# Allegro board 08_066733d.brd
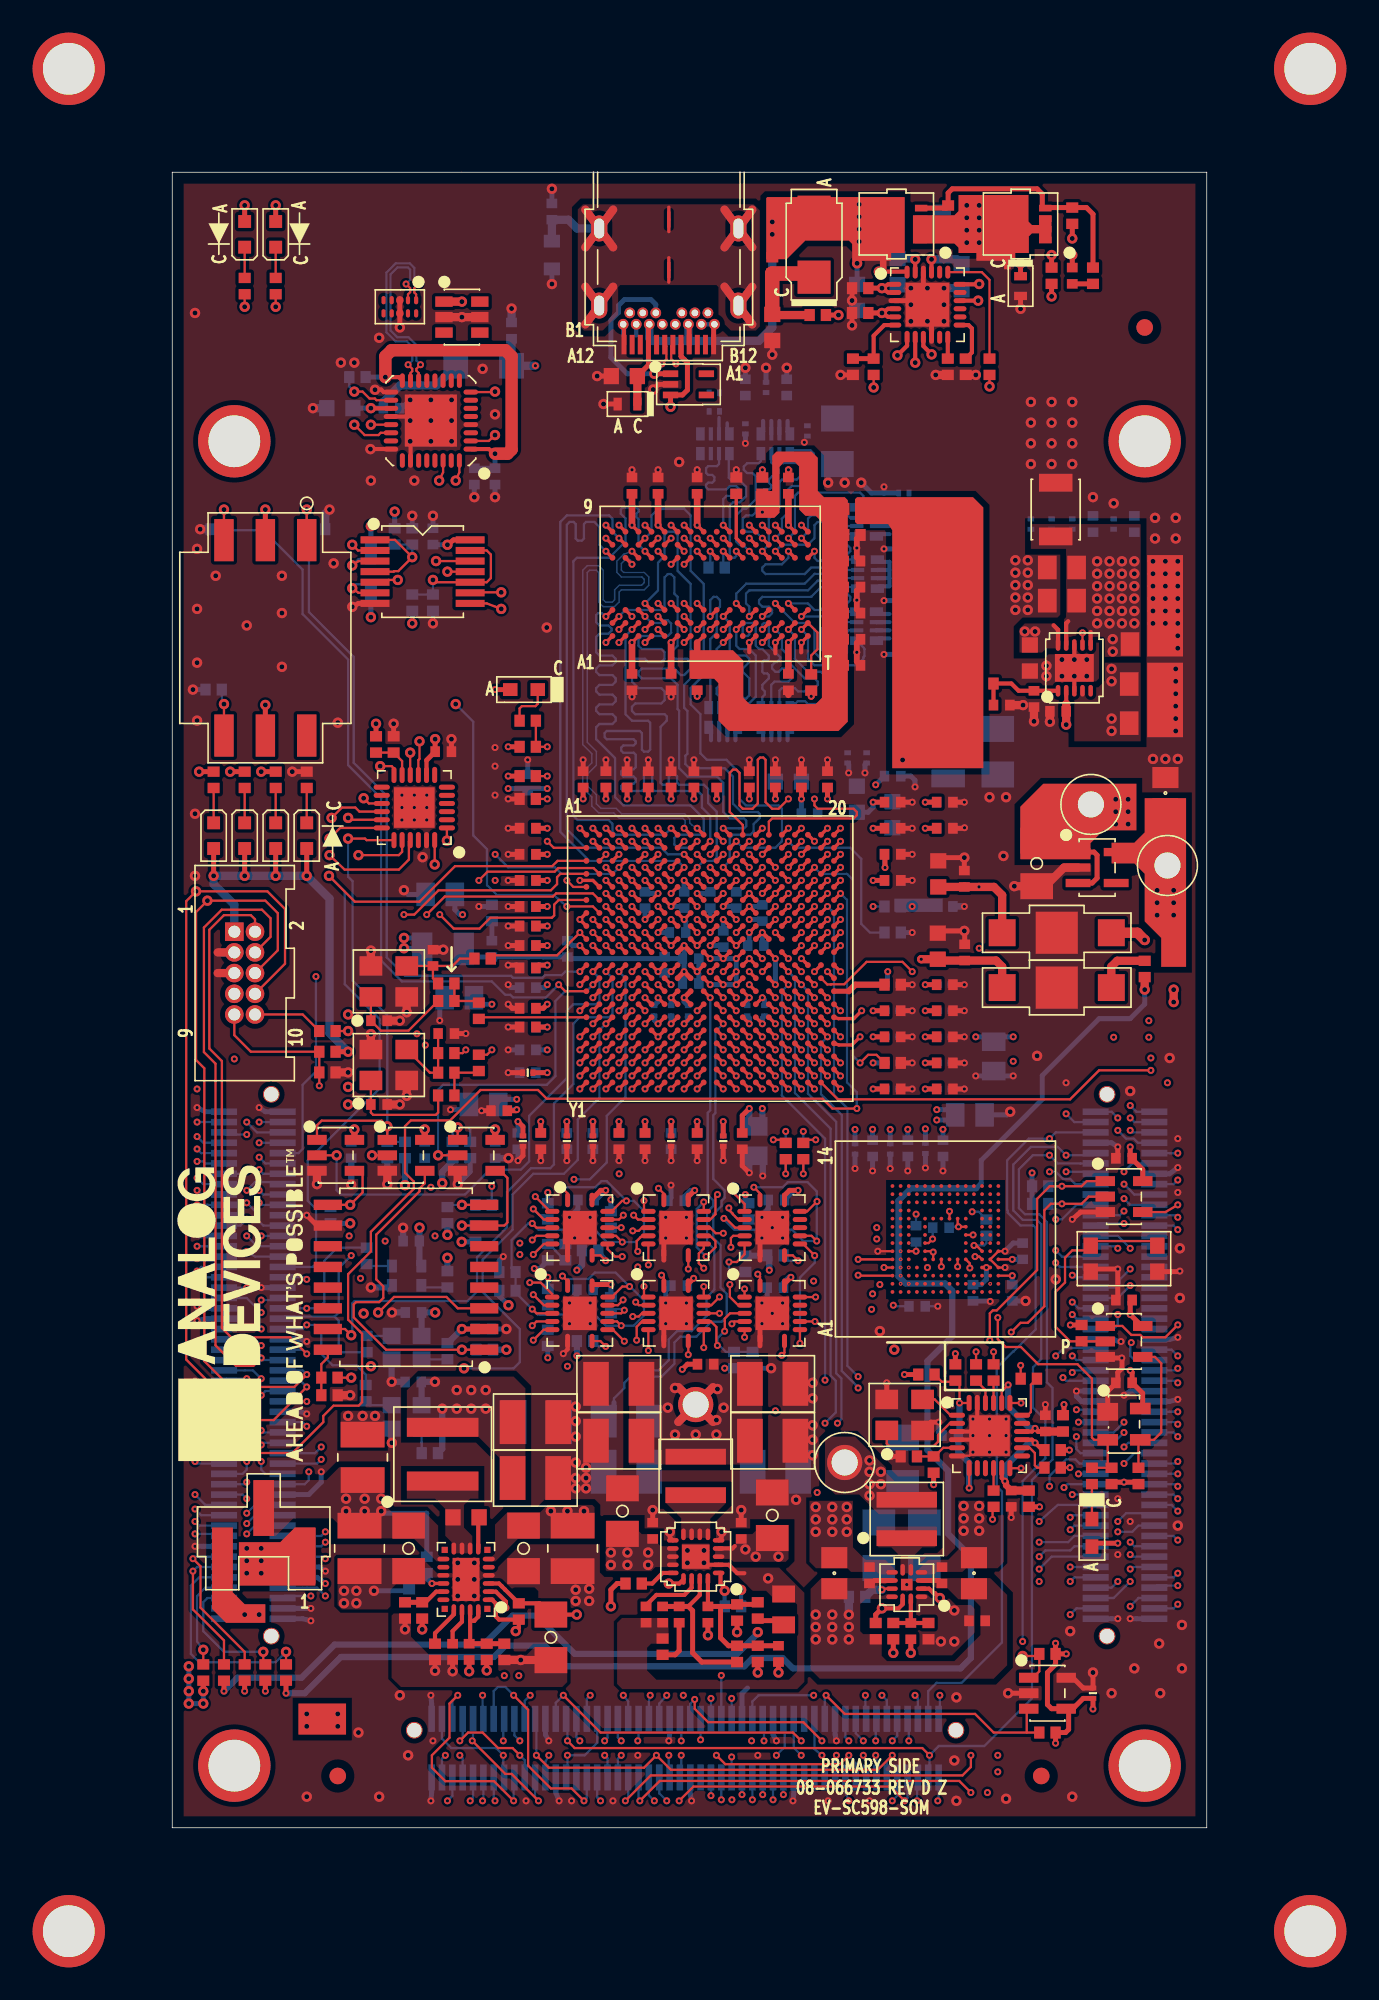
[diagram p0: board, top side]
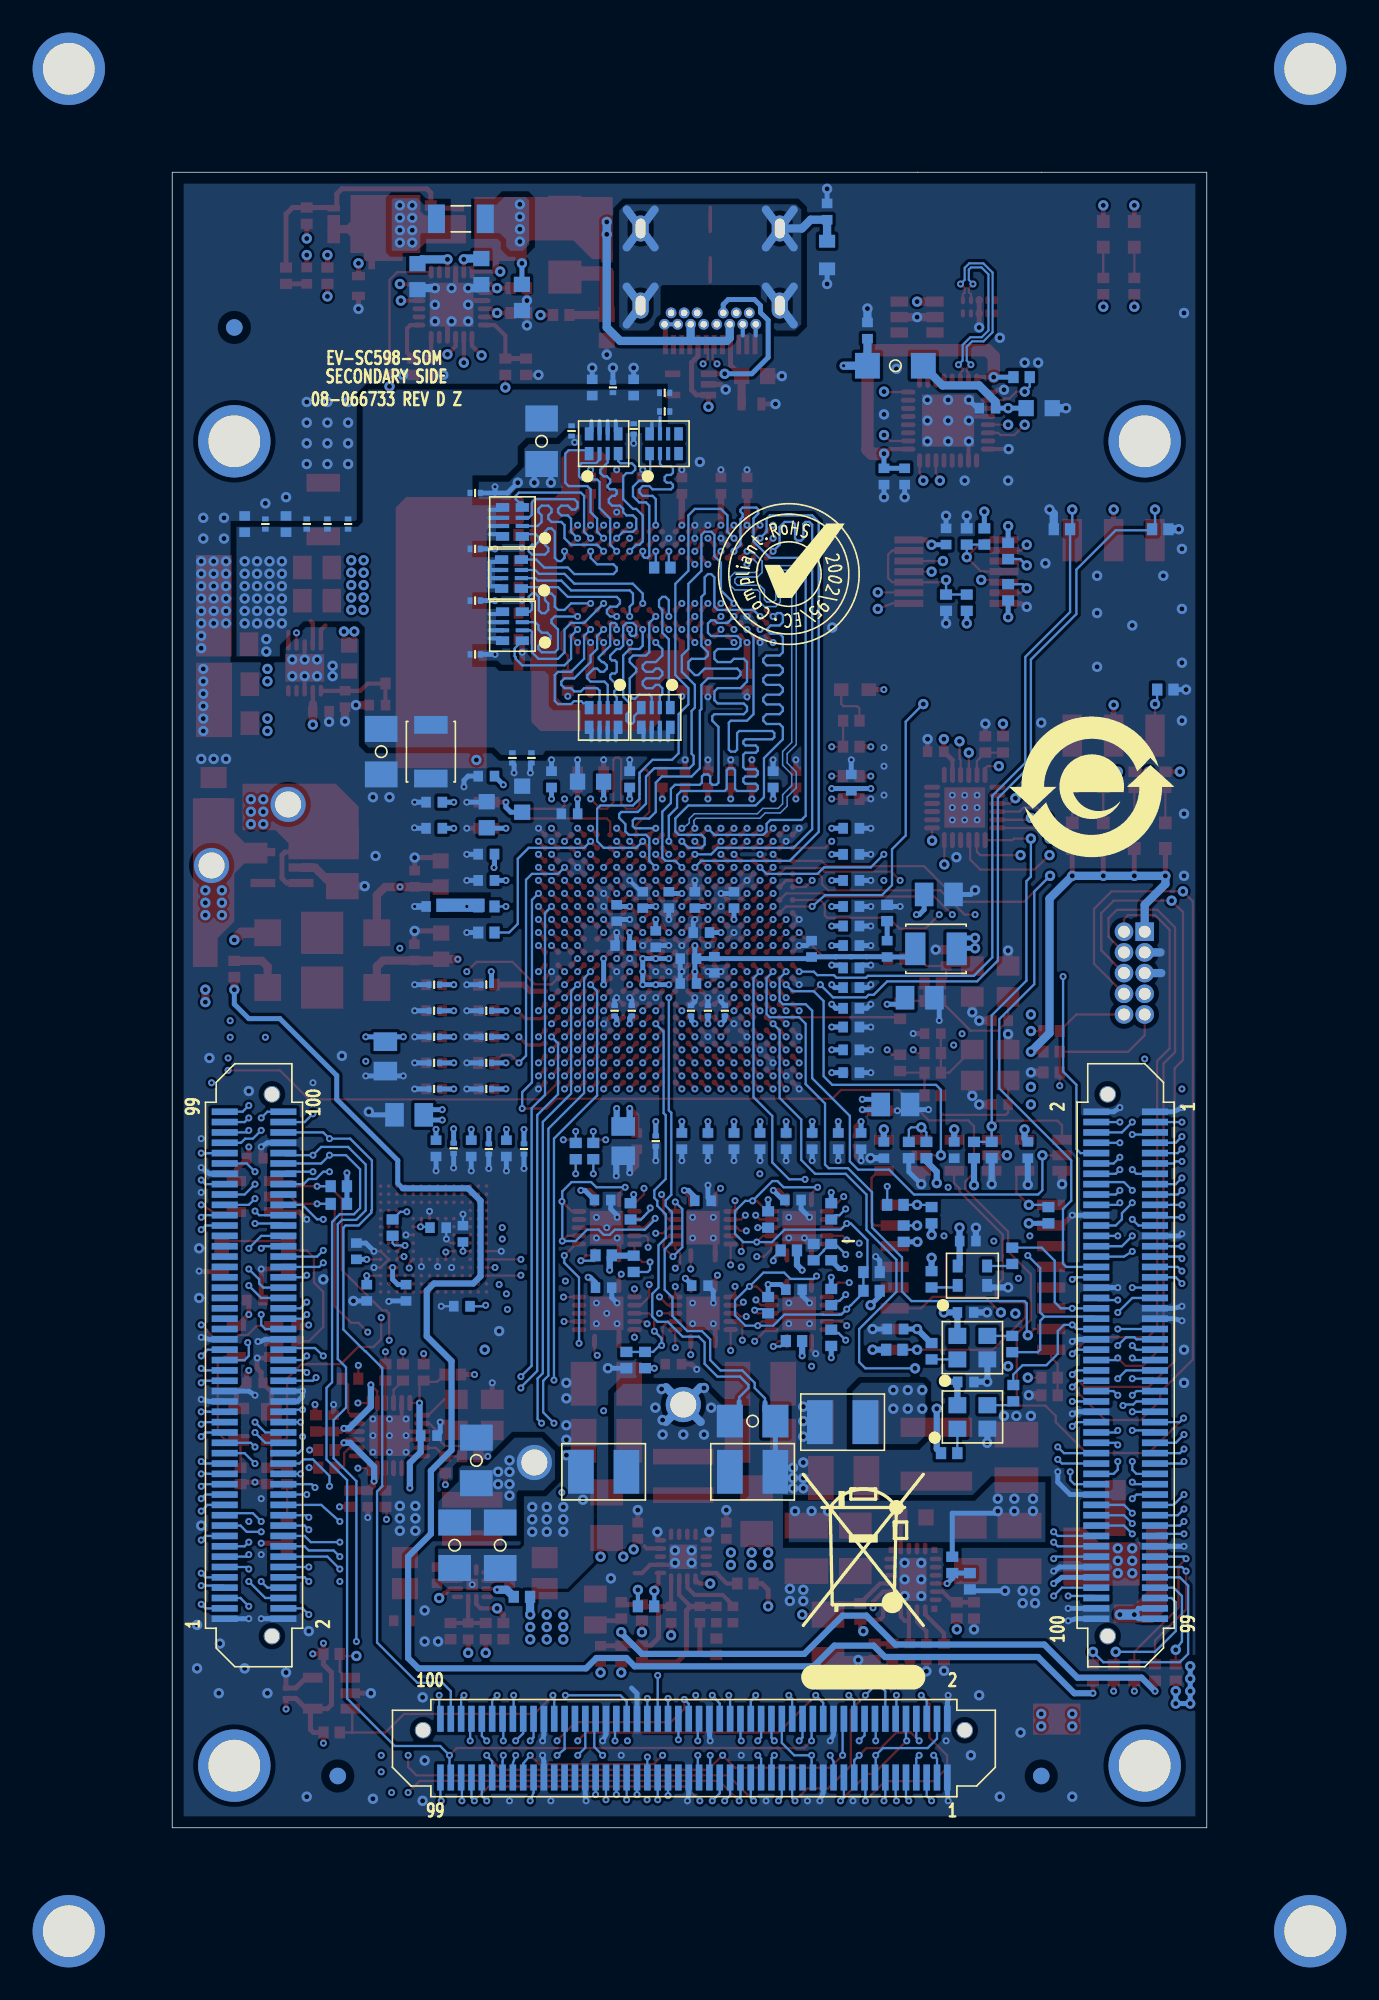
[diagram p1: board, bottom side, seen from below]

Outline 63.5 x 101.6 mm; copper layers: TOP, L2_PWR, L3_GND, L4_SIG, L5_SIG, L6_PWR, L7_SIG, L8_SIG, L9_GND, BOTTOM. Coordinates in mm from the lower left corner of the outline.
Outline path: 0,101.6 0,0 63.5,0 63.5,101.6 0,101.6

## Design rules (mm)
constraint set DEFAULT: min track width 0.14
net group DP_USB: nets USB_DM USB_DP
net group ADDRESS: nets DMC0_A00 DMC0_A01 DMC0_A02 DMC0_A03 DMC0_A04 DMC0_A05 DMC0_A06 DMC0_A07 DMC0_A08 DMC0_A09 DMC0_A10 DMC0_A11 DMC0_A12 DMC0_A13 DMC0_A14 DMC0_A15 DMC0_BA0 DMC0_BA1 DMC0_BA2 DMC0_CAS* DMC0_CKE DMC0_CS0* DMC0_ODT DMC0_RAS* DMC0_RESET* DMC0_WE*
net group DIGITAL: nets DMC0_CK DMC0_CK* DMC0_DQ00 DMC0_DQ01 DMC0_DQ02 DMC0_DQ03 DMC0_DQ04 DMC0_DQ05 DMC0_DQ06 DMC0_DQ07 DMC0_DQ08 DMC0_DQ09 DMC0_DQ10 DMC0_DQ11 DMC0_DQ12 DMC0_DQ13 DMC0_DQ14 DMC0_DQ15 DMC0_LDM DMC0_LDQS DMC0_LDQS* DMC0_UDM DMC0_UDQS DMC0_UDQS*

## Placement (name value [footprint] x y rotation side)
C1  0.1uF  [C0402]  28.22 82.37 90 top
C2  0.1uF  [C0402]  32.22 82.37 90 top
C3  0.1uF  [C0402]  37.82 82.37 90 top
C4  100pF  [C0402]  47.42 56.54 0 bottom
C5  0.1uF  [C0402]  29.82 82.37 90 top
C6  0.1uF  [C0402]  28.22 70.31 270 top
C7  0.1uF  [C0402]  30.62 70.31 270 top
C8  0.1uF  [C0402]  37.82 70.31 270 top
C9  0.01uF  [C0201]  44.91 81.92 180 bottom
C10  0.01uF  [C0201]  35.18 85.85 270 bottom
C11  10uF  [C0805H55]  59.64 67.79 0 top
C12  0.01uF  [C0201]  42.62 65.66 270 bottom
C13  10uF  [C0805H55]  59.64 70.19 0 top
C14  0.01uF  [C0201]  44.91 72.01 180 bottom
C15  4.7uF  [C1206H71]  50.67 66.04 270 bottom
C16  0.01uF  [C0201]  44.91 78.49 180 bottom
C17  4.7uF  [C1206H71]  40.83 85.09 270 bottom
C18  0.01uF  [C0201]  44.91 75.31 180 bottom
C19  100uF  [C1210H106]  47.62 66.04 270 bottom
C20  100uF  [C1210H106]  54.23 80.9 90 top
C21  0.01uF  [C0201]  38.99 85.73 270 bottom
C22  10uF  [C0805H55]  54.61 77.34 180 top
C23  0.01uF  [C0201]  41.45 65.66 270 bottom
C24  10uF  [C0805H55]  54.61 75.31 180 top
C25  0.01uF  [C0201]  33.27 88.06 180 bottom
C26  10uF  [C0805H55]  59.69 72.64 0 top
C27  1uF  [C0402]  52.9 69.28 270 top
C28  0.01uF  [C0402]  41.75 74.54 0 top
C29  0.01uF  [C0201]  33.27 86.92 180 bottom
C30  0.1uF  [C0402]  41.75 71.34 0 top
C31  0.01uF  [C0201]  52.71 80.01 90 bottom
C32  0.01uF  [C0402]  41.75 76.14 0 top
C33  0.01uF  [C0201]  55.25 80.01 90 bottom
C34  0.1uF  [C0402]  41.75 72.94 0 top
C35  0.01uF  [C0201]  57.79 80.01 90 bottom
C36  0.1uF  [C0402]  50.91 68.9 0 top
C37  0.1uF  [C0402]  59.05 80.01 90 bottom
C38  4.7uF  [C0603]  52.64 71.79 270 top
C39  0.1uF  [C0402]  32.22 70.31 90 top
C40  0.1uF  [C0402]  41.75 77.74 0 top
C41  1uF  [C0402]  56.52 80.01 90 bottom
C42  0.1uF  [C0402]  37.72 88.39 90 bottom
C43  1uF  [C0402]  35.18 88.39 90 bottom
C44  10uF  [C0603]  46.99 54.1 90 top
C45  0.1uF  [C0402]  48.64 53.72 90 top
C46  0.01uF  [C0402]  31.82 51.82 0 bottom
C47  0.1uF  [C0402]  19.62 53.94 90 bottom
C48  1uF  [C0402]  44.22 59.75 0 bottom
C49  10uF  [C0805H55]  48.96 43.75 0 bottom
C50  10uF  [C0805H55]  17.62 50.94 180 bottom
C51  1uF  [C0402]  21.82 54.14 180 bottom
C52  10uF  [C0805H55]  35.82 42.14 270 bottom
C53  1uF  [C0402]  21.82 64.14 90 bottom
C54  10uF  [C0805H55]  19.11 44.39 180 bottom
C55  10uF  [C0805H55]  16.45 57.28 180 bottom
C56  1uF  [C0402]  21.82 55.34 180 bottom
C57  10uF  [C0805H55]  50.42 47.34 270 bottom
C58  0.22uF  [C0402]  26.62 64.34 90 top
C59  0.47uF  [C0402]  31.02 54.94 0 bottom
C60  0.22uF  [C0402]  21.82 58.14 180 top
C61  1uF  [C0402]  21.82 51.56 180 bottom
C62  0.1uF  [C0402]  44.22 45.34 0 top
C63  0.22uF  [C0402]  39.12 62.23 0 bottom
C64  0.01uF  [C0201]  25.82 42.14 270 top
C65  0.22uF  [C0402]  29.02 56.94 90 bottom
C66  1uF  [C0402]  21.82 50.29 180 bottom
C67  0.1uF  [C0402]  47.42 50.14 0 top
C68  0.1uF  [C0402]  29.22 64.34 90 top
C69  0.22uF  [C0402]  35.42 64.34 90 top
C70  0.01uF  [C0201]  30.62 42.14 270 top
C71  0.22uF  [C0402]  21.82 46.34 180 bottom
C72  0.1uF  [C0402]  47.42 46.94 0 top
C73  0.1uF  [C0402]  27.92 64.34 90 top
C74  0.22uF  [C0402]  44.22 58.14 0 top
C75  0.1uF  [C0402]  22.62 42.14 270 bottom
C76  0.22uF  [C0402]  36.22 56.14 270 bottom
C77  0.1uF  [C0402]  47.42 51.74 0 top
C78  0.1uF  [C0402]  25.22 64.34 90 top
C79  0.22uF  [C0402]  37.02 64.34 90 top
C80  0.01uF  [C0201]  21.53 42.14 270 top
C81  0.22uF  [C0402]  21.82 59.74 180 top
C82  0.1uF  [C0402]  44.22 48.54 0 top
C83  0.1uF  [C0402]  30.62 64.34 90 top
C84  0.22uF  [C0402]  38.62 64.34 90 top
C85  0.01uF  [C0201]  46.23 41.7 270 bottom
C86  0.01uF  [C0201]  21.82 46.34 180 top
C87  0.1uF  [C0402]  47.42 45.34 0 top
C88  0.1uF  [C0402]  32.02 64.34 90 top
C89  0.1uF  [C0402]  44.22 58.14 0 bottom
C90  0.47uF  [C0402]  35.82 54.14 0 bottom
C91  0.1uF  [C0402]  21.82 55.34 180 top
C92  0.01uF  [C0201]  47.42 51.74 0 bottom
C93  0.1uF  [C0402]  33.42 64.34 90 top
C94  1000pF  [C0603]  44.2 62.17 90 bottom
C95  0.47uF  [C0402]  30.62 42.14 270 bottom
C96  0.1uF  [C0402]  21.82 54.14 180 top
C97  0.01uF  [C0201]  44.22 45.34 0 bottom
C98  0.1uF  [C0402]  44.22 64.54 0 bottom
C99  0.47uF  [C0402]  25.82 42.14 270 bottom
C100  0.1uF  [C0402]  21.82 52.77 180 top
C101  0.01uF  [C0201]  47.42 46.94 0 bottom
C102  1000pF  [C0603]  42.02 63.12 90 bottom
C103  0.47uF  [C0402]  21.22 42.14 270 bottom
C104  0.1uF  [C0402]  21.82 49.14 180 top
C105  0.01uF  [C0201]  47.42 50.14 0 bottom
C106  0.22uF  [C0402]  47.42 62.94 0 bottom
C107  0.01uF  [C0201]  44.07 41.66 270 bottom
C108  0.01uF  [C0201]  30.62 50.14 90 bottom
C109  0.1uF  [C0402]  34.99 42.14 270 top
C110  0.47uF  [C0402]  40.22 64.34 90 bottom
C111  0.47uF  [C0402]  45.15 41.7 270 bottom
C112  0.1uF  [C0402]  33.82 54.54 270 bottom
C113  0.01uF  [C0201]  44.22 50.14 0 bottom
C114  0.47uF  [C0402]  47.42 61.34 0 bottom
C115  0.47uF  [C0402]  47.31 41.7 270 bottom
C116  0.47uF  [C0402]  21.82 56.54 180 top
C117  0.01uF  [C0201]  33.82 42.14 270 bottom
C118  0.1uF  [C0402]  34.62 56.94 90 bottom
C119  0.47uF  [C0402]  42.99 41.7 270 bottom
C120  0.47uF  [C0402]  21.82 61.34 180 top
C121  0.01uF  [C0201]  44.22 46.94 0 bottom
C122  0.1uF  [C0402]  31.42 56.94 90 bottom
C123  0.22uF  [C0402]  29.02 42.14 270 bottom
C124  0.47uF  [C0402]  21.82 56.54 180 bottom
C125  0.01uF  [C0201]  47.42 45.34 0 bottom
C126  0.22uF  [C0402]  26.62 64.34 90 bottom
C127  0.01uF  [C0201]  24.22 42.14 270 top
C128  0.01uF  [C0201]  35.29 50.14 90 bottom
C129  0.1uF  [C0402]  47.42 48.54 0 top
C130  0.47uF  [C0402]  47.42 62.94 0 top
C131  0.22uF  [C0402]  24.22 42.14 270 bottom
C132  0.01uF  [C0201]  31.66 50.14 90 bottom
C133  0.1uF  [C0402]  44.22 50.14 0 top
C134  0.1uF  [C0402]  44.22 61.34 0 top
C135  0.22uF  [C0402]  29.02 42.14 270 top
C136  0.01uF  [C0201]  36.35 50.14 90 bottom
C137  0.01uF  [C0201]  44.22 51.74 0 bottom
C138  0.1uF  [C0402]  44.22 59.74 0 top
C139  0.22uF  [C0402]  32.22 42.14 270 top
C140  0.47uF  [C0402]  21.82 52.77 180 bottom
C141  0.01uF  [C0201]  47.42 48.54 0 bottom
C142  0.1uF  [C0402]  35.42 64.34 90 bottom
C143  0.22uF  [C0402]  27.42 42.14 270 top
C144  0.47uF  [C0402]  21.82 59.74 180 bottom
C145  0.01uF  [C0201]  44.22 48.54 0 bottom
C146  0.22uF  [C0402]  47.42 61.34 0 top
C147  0.01uF  [C0201]  41.91 41.66 270 bottom
C148  0.47uF  [C0402]  21.82 47.74 180 bottom
C149  0.01uF  [C0201]  33.82 42.14 270 top
C150  0.47uF  [C0402]  40.22 64.34 90 top
C151  0.22uF  [C0402]  27.42 42.14 270 bottom
C152  0.01uF  [C0201]  29.58 50.14 90 bottom
C153  0.1uF  [C0402]  44.22 62.94 0 top
C154  0.22uF  [C0402]  32.22 42.14 270 bottom
C155  0.47uF  [C0402]  21.82 61.34 180 bottom
C156  0.1uF  [C0402]  33.02 56.94 270 bottom
C157  0.22uF  [C0402]  20.07 44.01 180 top
C158  4.7uF  [C0603]  27.75 89.09 180 top
C159  1uF  [C0603]  36.83 92.08 270 top
C160  0.1uF  [C0402]  55.25 95.25 270 top
C161  0.47uF  [C0402]  21.82 49.14 180 bottom
C162  1000pF  [C0603]  37.82 64.2 0 bottom
C163  0.22uF  [C0402]  22.62 42.14 270 top
C164  0.47uF  [C0402]  21.82 50.29 180 top
C165  0.47uF  [C0402]  21.82 58.14 180 bottom
C166  27pF  [C0402]  12.69 49.53 0 top
C167  27pF  [C0402]  12.69 44.39 0 top
C168  27pF  [C0402]  16 53.39 90 top
C169  27pF  [C0402]  16.82 48.74 0 top
C170  0.1uF  [C0402]  47.75 24.07 180 bottom
C171  0.1uF  [C0402]  53.59 24.82 90 top
C172  0.1uF  [C0402]  51.5 20.19 270 top
C173  0.01uF  [C0402]  15.5 41.59 270 bottom
C174  0.01uF  [C0402]  10.99 41.59 270 bottom
C175  0.01uF  [C0402]  19.82 41.59 270 bottom
C176  0.01uF  [C0402]  19.11 30.61 0 bottom
C177  10uF  [C0603]  47.02 58.54 90 top
C178  0.1uF  [C0402]  48.62 58.24 90 top
C179  0.01uF  [C0402]  16.64 66.04 0 top
C180  0.01uF  [C0402]  58.42 41.08 180 top
C181  0.01uF  [C0402]  58.42 32.38 180 top
C182  0.01uF  [C0402]  58.42 27.3 180 top
C183  0.1uF  [C0402]  20.83 91.88 90 bottom
C184  0.01uF  [C0402]  23.3 99.19 90 bottom
C185  4.7uF  [C0603]  10.29 87.12 180 bottom
C186  0.1uF  [C0402]  13.46 87.12 0 bottom
C187  0.1uF  [C0402]  19.81 82.93 270 bottom
C188  0.01uF  [C0402]  18.54 82.93 270 bottom
C189  0.01uF  [C0402]  16 79.25 90 bottom
C190  10uF  [C1210-2]  11.68 22.73 90 top
C191  0.22uF  [C0402]  34.92 18.22 90 top
C192  0.22uF  [C0402]  29.49 18.22 90 top
C193  3.3pF  [C0402]  30.1 13.08 270 top
C194  22uF  [C1206H71]  27.64 19.43 90 top
C195  270pF  [C0402]  31.11 13.08 270 top
C196  1uF  [C1206H71]  14.51 17.14 270 top
C197  22uF  [C1206H71]  36.83 19.18 90 top
C198  1uF  [C1206H71]  21.56 17.14 270 top
C199  1uF  [C0603]  48.45 95.19 270 bottom
C200  1uF  [C0603]  44.53 95.5 270 bottom
C201  1uF  [C0603]  42.04 93.92 270 bottom
C202  0.1uF  [C0402]  29.08 13.08 270 top
C203  10uF  [C1210-2]  11.49 17.14 270 top
C204  1500pF  [C0402]  17.21 10.79 270 top
C205  10uF  [C1210-2]  24.57 17.14 270 top
C206  1uF  [C1206H71]  23.24 11.68 270 top
C207  0.1uF  [C0603]  18.03 19.05 180 top
C208  100pF  [C0402]  32.88 13.08 90 top
C209  100pF  [C0402]  37.21 10.67 270 top
C210  47pF  [C0402]  18.22 10.79 90 top
C211  47uF  [C1210H95]  27.41 23.75 180 top
C212  1uF  [C1206H71]  27.88 24.96 180 bottom
C213  47uF  [C1210H95]  22.29 21.46 0 top
C214  47uF  [C1210H95]  27.41 27.24 180 top
C215  0.1uF  [C0402]  47.24 15.49 90 top
C216  47uF  [C1210H95]  22.29 24.89 0 top
C217  47uF  [C1210H95]  36.86 23.75 0 top
C218  0.1uF  [C0402]  42.8 15.49 90 top
C219  47uF  [C1210H95]  22.35 24.89 0 bottom
C220  2.2pF  [C0402]  45.33 12.07 90 top
C221  47uF  [C1210H95]  27.88 21.84 180 bottom
C222  4.7uF  [C0805H60]  40.64 15.62 90 top
C223  47uF  [C1210H95]  37.02 21.84 0 bottom
C224  22uF  [C1206H71]  46.16 17.34 270 bottom
C225  4.7uF  [C0805H60]  49.21 15.62 90 top
C226  47uF  [C1210H95]  36.86 27.24 0 top
C227  22uF  [C1206H71]  44.83 22.54 90 bottom
C228  1uF  [C1206H71]  53.06 59.18 270 top
C229  0.1uF  [C0402]  32.74 28.45 180 top
C230  22uF  [C1206H71]  43.37 17.34 270 bottom
C231  4.7uF  [C0805H60]  60.96 63.5 90 top
C232  1uF  [C0402]  45.72 32 0 bottom
C233  1uF  [C0402]  52.2 35.38 90 bottom
C234  0.1uF  [C0402]  47.18 36.83 180 bottom
C235  0.1uF  [C0402]  45.66 36.45 90 bottom
C236  0.1uF  [C0402]  49.15 32.83 270 bottom
C237  0.1uF  [C0402]  51.56 32.83 270 bottom
C238  0.1uF  [C0402]  25.4 38.53 180 bottom
C239  0.1uF  [C0402]  30.92 38.48 180 bottom
C240  0.1uF  [C0402]  25.34 33.02 180 bottom
C241  0.1uF  [C0402]  31.11 33.27 180 bottom
C242  0.1uF  [C0402]  30.23 52.96 270 bottom
C243  0.1uF  [C0402]  24.26 53.94 90 bottom
C244  0.01uF  [C0402]  31.82 53.34 0 bottom
C245  0.01uF  [C0201]  53.98 80.01 90 bottom
C246  0.01uF  [C0201]  36.45 88.39 90 bottom
C247  0.01uF  [C0201]  56.52 8.26 90 top
C248  0.1uF  [C0402]  49.4 12.7 180 top
C249  0.1uF  [C0402]  37.08 38.53 180 bottom
C250  0.1uF  [C0402]  37.02 33.15 180 bottom
C251  0.1uF  [C0402]  14.67 36 180 bottom
C252  0.1uF  [C0402]  14.81 31.62 180 bottom
C253  0.1uF  [C0402]  14.79 27.36 180 bottom
C254  1uF  [C0402]  54.37 68.52 180 top
D1  ESDA6V1SC6Y  [SOT23_6-3]  17.78 92.71 270 top
D2  SZESD7004MUTAG  [UDFN10_2_5X1]  13.97 93.34 180 top
D15  ESDA25P35-1U1M  [DFN2_1_6X1]  27.95 87.38 180 top
D16  NRVTSA3100ET3G  [SMA]  39.4 97.16 90 top
D17  ESDA25W5  [SC70-5_A]  31.69 88.58 270 top
D18  ESDA25P35-1U1M  [DFN2_1_6X1]  52.07 94.62 270 top
DS1  SML-D13FWT86C  [LED0603-2]  6.35 60.88 270 top
DS2  SML-D13FWT86C  [LED0603-2]  4.45 60.88 270 top
DS3  SML-D13FWT86C  [LED0603-2]  2.54 60.88 270 top
DS4  SML-D13FWT86C  [LED0603-2]  8.26 60.88 270 top
DS5  SML-D14U2WT86C  [LED0603_A]  56.45 18.1 270 top
DS6  SML-D14U2WT86C  [LED0603_A]  21.59 69.85 180 top
DS7  LY L296-Q2R2-26-Z  [LED0603-2]  4.45 97.79 90 top
DS8  LY L296-Q2R2-26-Z  [LED0603-2]  6.35 97.79 90 top
E1  600OHM  [L1206]  19.11 89.73 180 bottom
FL1  4700pF  [F2606]  54.29 51.56 180 top
FL2  4700pF  [F2606]  54.29 54.93 180 top
J1  A-LSS-150-01-L-DV-A-K  [CNSAMTECLSS-150-01-X-DV-A]  58.48 28.39 90 bottom
J2  A-LSS-150-01-L-DV-A-K  [CNSAMTECLSS-150-01-X-DV-A]  31.48 4.88 0 bottom
J3  A-LSS-150-01-L-DV-A-K  [CNSAMTECLSS-150-01-X-DV-A]  4.98 28.39 270 bottom
JP1  TSM-103-01-H-SV  [CNSMMHDR1X3L300W100H403]  5.61 18.16 180 top
L1  10UH  [L1210H67]  16.62 53.94 0 bottom
L2  0.1UH  [LSMSQ157H122]  32.13 21.59 90 top
L3  1uH  [LSML208W216H122]  16.6 22.92 90 top
L4  220NH  [LSMSQ157H83_A]  45.09 18.95 90 top
NOREF  -  [unnamed]  -6.35 -6.35 0 top
NOREF#2  -  [#2]  16.99 -82.2 0 top
NOREF#3  -  [#2]  0 101.6 0 top
NOREF#4  -  [#2]  -111.76 -130.81 0 top
NOREF#5  -  [unnamed]  3.81 3.81 0 top
NOREF#6  -  [#2]  52.2 -18.73 90 top
NOREF#7  -  [#2]  11.3 120.33 270 top
NOREF#8  -  [unnamed]  3.81 85.09 0 top
NOREF#9  -  [#2]  34.67 -51.88 0 top
NOREF#10  -  [#2]  42.93 2.1 270 top
NOREF#11  -  [unnamed]  10.16 3.17 0 top
NOREF#12  -  [#2]  63.5 0 0 top
NOREF#13  -  [#2]  0 0 0 top
NOREF#14  -  [#2]  -111.76 -130.81 0 top
NOREF#15  -  [unnamed]  53.34 3.17 0 top
NOREF#16  -  [unnamed]  59.69 85.09 0 top
NOREF#17  -  [unnamed]  69.85 -6.35 0 top
NOREF#18  -  [#2]  0 0 0 top
NOREF#19  -  [#2]  4.19 32.07 90 top
NOREF#20  -  [#2]  -95.19 32.64 0 top
NOREF#21  -  [#2]  0 -12.7 0 top
NOREF#22  -  [#2]  -111.76 -130.81 0 top
NOREF#23  -  [#2]  93.34 193.29 0 top
NOREF#24  -  [#2]  17.3 -86.01 0 top
NOREF#25  -  [#2]  134.68 145.73 0 top
NOREF#26  -  [#2]  -18.73 11.3 0 top
NOREF#27  -  [unnamed]  -6.35 107.95 0 top
NOREF#28  -  [#2]  76.2 -12.7 0 top
NOREF#29  -  [#2]  3.81 3.81 0 top
NOREF#30  -  [#2]  276.66 378.88 0 top
NOREF#31  -  [#2]  -12.7 -12.7 0 top
NOREF#32  -  [#2]  -12.7 114.3 0 top
NOREF#33  -  [#2]  -12.7 101.6 0 top
NOREF#34  -  [#2]  -12.7 -12.7 0 top
NOREF#35  -  [#2]  -48.58 269.75 0 top
NOREF#36  -  [#2]  -12.7 114.3 0 top
NOREF#37  -  [#2]  -209.55 -209.55 0 top
NOREF#38  -  [#2]  63.5 -12.7 0 top
NOREF#39  -  [#2]  -12.7 0 0 top
NOREF#40  -  [#2]  168.21 89.28 0 top
NOREF#41  -  [#2]  76.2 -12.7 90 top
NOREF#42  -  [#2]  82.23 90.3 180 top
NOREF#43  -  [#2]  -111.76 -130.81 0 top
NOREF#44  -  [unnamed]  69.85 107.95 0 top
NOREF#45  -  [#2]  3.81 3.81 0 top
NOREF#46  -  [unnamed]  59.69 92.08 0 top
NOREF#47  -  [unnamed]  59.69 3.81 0 top
NOREF#48  -  [#2]  7.06 63.88 180 bottom
NOREF#49  -  [unnamed]  53.34 3.17 180 bottom
NOREF#50  -  [unnamed]  59.69 92.08 180 bottom
NOREF#51  -  [#2]  25.65 76.94 180 bottom
NOREF#52  -  [#2]  11.81 25.37 180 bottom
NOREF#53  -  [unnamed]  10.16 3.17 180 bottom
P1  632723300011  [CNWURTH632723300011]  30.48 95.6 180 top
P6  SHF-105-01-L-D-TH-TR  [CNTHMHDR2X5L500W200H215]  3.81 54.99 270 top
Q4  STL6P3LLH6  [POWERFLAT_33X33]  44.45 98.42 90 top
Q5  STL6P3LLH6  [POWERFLAT_33X33]  52.07 98.42 90 top
R1  34  [R0402]  44.22 54.94 0 bottom
R2  2K  [R0402]  44.22 56.54 180 bottom
R3  200  [R0402]  33.42 77.34 0 bottom
R4  240  [R0402]  34.62 82.37 90 top
R5  0  [R0402]  42.04 14.17 0 bottom
R6  5.1K  [R0402]  42.23 94.49 180 top
R7  0  [R0402]  49.91 70.22 180 top
R8  10K  [R0402]  39.22 70.29 90 top
R9  1K  [R0402]  36.22 82.37 270 top
R10  1K  [R0402]  41.75 79.34 0 top
R11  1K  [R0402]  41.75 80.94 0 top
R12  100  [R0402]  38.73 41.53 270 bottom
R13  100  [R0402]  37.66 41.53 270 bottom
R14  2.2K  [R0402]  38.73 41.53 270 top
R15  2.2K  [R0402]  37.66 41.53 270 top
R16  0  [R0402]  59.69 52.71 90 top
R17  20  [R0402]  19.62 56.14 90 bottom
R18  0  [R0402]  18.82 50.14 90 top
R19  0  [R0402]  18.82 46.94 270 top
R20  1.2K  [R0402]  16.82 50.74 180 top
R21  1.2K  [R0402]  16.82 44.94 180 top
R22  499K  [R0402]  16.82 51.82 180 top
R23  499K  [R0402]  16.82 46.34 180 top
R24  10K  [R0402]  8.89 79.69 0 bottom
R25  10K  [R0402]  2.54 69.85 180 bottom
R26  10K  [R0402]  2.86 79.69 180 bottom
R27  0  [R0402]  19.05 53.34 0 top
R28  0  [R0402]  16.82 47.54 0 top
R29  0  [R0402]  48.07 27.94 270 top
R30  3.01K  [R0402]  46.74 22.29 90 top
R31  1.5K  [R0402]  45.21 22.79 180 top
R32  0  [R0402]  46.29 27.81 0 top
R33  0  [R0402]  54.67 24.82 270 top
R34  0  [R0402]  49.34 27.94 90 top
R35  0  [R0402]  52.58 27.56 180 top
R36  0  [R0402]  54.04 22.1 0 top
R37  0  [R0402]  50.41 20.19 270 top
R38  0  [R0402]  52.58 20.19 90 top
R39  0  [R0402]  54.04 23.18 180 top
R40  0  [R0402]  50.41 27.94 90 top
R41  0  [R0402]  4.45 9.53 90 top
R42  0  [R0402]  3.17 9.53 90 top
R43  0  [R0402]  6.98 9.53 90 top
R44  0  [R0402]  1.91 9.53 90 top
R45  0  [R0402]  5.71 9.53 90 top
R46  10K  [R0402]  18.61 36.46 90 bottom
R47  10K  [R0402]  19.18 29.34 180 bottom
R48  10K  [R0402]  9.72 37.59 90 bottom
R49  33  [R0402]  9.65 27.62 180 top
R50  10K  [R0402]  9.65 26.54 0 top
R51  10K  [R0402]  16.89 37.59 90 bottom
R52  33  [R0402]  19.11 38.23 0 bottom
R53  100K  [R0402]  14.29 41.59 90 bottom
R54  100K  [R0402]  13.2 41.59 270 bottom
R55  100K  [R0402]  17.21 41.59 90 bottom
R56  100K  [R0402]  18.29 41.59 270 bottom
R57  10K  [R0402]  21.82 63.14 180 top
R58  0  [R0402]  44.22 51.74 0 top
R59  330  [R0402]  21.82 67.94 0 top
R60  10K  [R0402]  21.82 66.34 0 top
R61  10K  [R0402]  21.82 64.54 0 top
R62  10K  [R0402]  53.28 38.29 0 bottom
R63  10K  [R0402]  53.28 39.37 0 bottom
R64  1.5K  [R0402]  12.51 66.48 270 top
R65  100  [R0402]  13.59 66.48 90 top
R66  5.1K  [R0402]  42.23 92.96 180 top
R67  0  [R1206]  45.78 98.74 0 bottom
R68  10K  [R0402]  24.13 35.33 90 bottom
R70  10K  [R0402]  55.82 30.35 270 top
R71  10K  [R0402]  59.31 21.59 90 top
R72  330  [R0402]  2.54 64.31 90 top
R73  330  [R0402]  56.45 21.59 90 top
R74  330  [R0402]  4.45 64.31 90 top
R75  10K  [R0402]  57.66 21.59 90 top
R76  330  [R0402]  6.35 64.31 90 top
R77  330  [R0402]  8.26 64.31 90 top
R78  10K  [R0402]  9.53 47.62 180 top
R79  10K  [R0402]  9.53 46.36 0 top
R80  1MEG  [R0603]  23.3 96.52 270 bottom
R81  100K  [R0402]  14.73 75.18 90 bottom
R82  100K  [R0402]  16 75.18 270 bottom
R83  100K  [R0402]  13.65 79.25 270 bottom
R84  100K  [R0402]  14.73 79.25 90 bottom
R85  0  [R0402]  9.53 48.9 0 top
R86  10K  [R0402]  12.19 78.36 270 bottom
R87  10K  [R0402]  12.19 75.82 90 bottom
R88  0  [R0402]  11.37 89.03 180 bottom
R89  330  [R0402]  4.45 94.62 270 top
R90  330  [R0402]  6.35 94.62 270 top
R91  37.4K  [R0402]  30.1 11.11 90 top
R92  0  [R0402]  34.42 13.59 180 bottom
R93  0  [R0402]  14.29 13.34 270 top
R94  0  [R0402]  15.34 13.34 270 top
R95  38.3K  [R0402]  14.54 15.13 90 bottom
R96  100K  [R0402]  15.62 16.13 270 bottom
R97  1.69MEG  [R0402]  34.67 10.67 90 top
R98  15.8K  [R0402]  16.13 10.79 270 top
R99  100K  [R0402]  28.32 14.99 180 top
R100  100K  [R0402]  21.27 13.27 90 top
R101  100K  [R0402]  34.67 13.21 90 top
R102  91K  [R0402]  35.94 13.34 270 top
R103  9K  [R0805]  37.53 13.4 90 top
R104  100K  [R0402]  43.18 12.07 270 top
R105  100K  [R0402]  19.3 10.79 90 top
R106  41.2K  [R0402]  20.38 10.79 270 top
R107  100K  [R0402]  35.94 10.67 270 top
R108  100K  [R0402]  44.26 12.07 90 top
R109  56.2K  [R0402]  46.42 12.07 270 top
R110  33  [R0402]  49.97 36.83 270 bottom
R111  0  [R0402]  43.05 89.66 90 top
R112  0  [R0402]  50.16 89.66 270 top
R113  6.98K  [R0402]  44.22 46.94 0 top
R114  100K  [R0402]  20.57 32.96 0 bottom
R115  100K  [R0402]  20.57 34.1 180 bottom
R116  100K  [R0402]  34.48 28.7 90 bottom
R117  100K  [R0402]  35.62 28.7 270 bottom
R118  10K  [R0402]  23.05 37.83 270 bottom
R119  10K  [R0402]  23.05 35.33 90 bottom
R120  10K  [R0402]  25.65 35.43 0 bottom
R121  10K  [R0402]  26.92 37.33 270 bottom
R122  10K  [R0402]  23.05 32.57 270 bottom
R123  470  [R0402]  36.83 95.89 270 top
R124  1K  [R0402]  39.62 92.84 0 top
R125  100K  [R0402]  47.6 89.66 270 top
R126  100K  [R0402]  48.7 89.66 270 top
R127  100K  [R0402]  41.78 89.66 270 top
R128  100K  [R0402]  47.62 99.06 90 top
R129  22K  [R0402]  55.25 98.93 270 top
R130  100  [R0402]  56.52 95.25 270 top
R131  10K  [R0402]  23.05 30.07 90 bottom
R132  10K  [R0402]  25.34 29.87 0 bottom
R133  10K  [R0402]  26.92 32.07 270 bottom
R134  10K  [R0402]  35.37 37.83 270 bottom
R135  10K  [R0402]  35.18 34.61 270 bottom
R136  3.3K  [R0402]  53.72 10.67 180 top
R137  3.3K  [R0402]  53.72 5.84 180 top
R138  10K  [R0402]  37.02 35.13 0 bottom
R139  10K  [R0402]  16.89 33.66 270 bottom
R140  10K  [R0402]  16.89 29.24 270 bottom
R141  0  [R0402]  11.94 35.1 90 bottom
R142  0  [R0402]  11.94 29.68 270 bottom
R143  10K  [R0402]  15.81 22.99 180 bottom
R144  0  [R0402]  11.87 26.67 90 bottom
R146  1K  [R0402]  53.98 95.25 270 top
RN1  100  [RESNET8]  42.68 76.94 90 bottom
RN2  100  [RESNET8]  42.62 73.74 90 bottom
RN3  100  [RESNET8]  42.62 80.14 90 bottom
RN4  100  [RESNET8]  37.02 84.94 180 bottom
RN5  100  [RESNET8]  37.02 68.14 0 bottom
RN6  100  [RESNET8]  33.82 68.14 0 bottom
RN7  100  [RESNET8]  33.31 84.94 180 bottom
S1  RDTAR10S1R  [SWSMSQ394H268]  5.71 73.03 180 top
S2  KMR223GLFG  [SWSML165W110H75]  58.42 34.92 0 top
TP1  WHT  [CNLOOPTP]  56.39 62.8 0 top
TP2  WHT  [CNLOOPTP]  32.13 25.97 0 top
TP3  WHT  [CNLOOPTP]  41.28 22.42 0 top
TP4  WHT  [CNLOOPTP]  61.09 59.05 0 top
U1  ADSP-SC598-BPZENG  [CSPBGA400_17X17]  33.02 53.34 270 top
U2  MIC5166YML-TR  [DFN10_3X3_PAD2_4X1_7]  55.37 71.18 0 top
U3  SI5356A-B03215-GM  [QFN24_4X4_PAD2_5X2_5]  50.16 24.07 270 top
U4  IS25LP512M-RMLA3  [SO16WB]  14.35 33.78 90 top
U5  74CBTLV1G125DBVRQ1  [SOT23-5L-2]  14.35 41.27 270 top
U6  STUSB4500QTR  [QFN24_4X4_PAD2_7X2_7]  46.36 93.47 270 top
U7  PI3C3125LEX  [TSSOP14]  15.37 77.09 270 top
U8  IS43TR16256BL-107MBL  [BGA96_13X9]  33.02 76.34 0 top
U9  74CBTLV1G125DBVRQ1  [SOT23-5L-2]  18.67 41.27 270 top
U10  74CBTLV1G125DBVRQ1  [SOT23-5L-2]  10.03 41.27 270 top
U11  SN74LVC1G08QDBVRQ1  [SOT23-5L-2]  58.42 38.73 270 top
U12  SN74CB3T3125RGYR  [QFN14_3_5X3_5_PAD2_05X2_05]  25.02 36.83 270 top
U13  SN74LVC1G08QDBVRQ1  [SOT23-5L-2]  58.42 29.84 270 top
U14  ADM6315-29D2ARTZR7  [SOT143A]  58.42 24.76 270 top
U15  FT232RQ  [QFN32_5X5_PAD3_2X3_2]  15.88 86.36 90 top
U16  LTC3310JV#WPBF  [QFN18_3X3_PAD1_51X1_7]  32.13 16.64 90 top
U17  LTC3307AHV#WTRMPBF  [QFN12_2X2_PAD0_7X0_7]  45.09 14.92 90 top
U18  ADP151AUJZ-1.8-R7  [TSOT-5]  56.77 58.93 270 top
U19  IS21ES04G  [BGA153_13X11_50]  47.46 36.13 0 top
U20  SN74CB3T3125RGYR  [QFN14_3_5X3_5_PAD2_05X2_05]  30.92 36.83 270 top
U21  SN74CB3T3125RGYR  [QFN14_3_5X3_5_PAD2_05X2_05]  25.02 31.57 270 top
U22  SN74CB3T3125RGYR  [QFN14_3_5X3_5_PAD2_05X2_05]  30.92 31.57 270 top
U23  SN74CB3T3125RGYR  [QFN14_3_5X3_5_PAD2_05X2_05]  36.83 36.83 270 top
U24  MCP23018-E/MJ  [QFN24_4X4_PAD2_5X2_5]  14.86 62.61 90 top
U25  SN74CB3T3125RGYR  [QFN14_3_5X3_5_PAD2_05X2_05]  36.83 31.57 270 top
U26  24AA01T-I/OT  [SOT23-5L-2]  53.72 8.26 270 top
VR1  LT8636EV#WPBF  [LQFN20_4X3_PAD2_65X1_65]  18.03 15.24 90 top
Y1  25MEGHZ  [YSML126W98H31]  13.29 51.94 0 top
Y2  25MEGHZ  [YSML126W98H31]  13.29 46.81 0 top
Y3  25MEGHZ  [YSML126W98H31]  44.96 25.34 0 top
Y4  24.576MEGHZ  [YSML79W63H31]  14.38 33.88 180 bottom
Y5  25MEGHZ  [YSML98W79H35]  14.38 29.46 180 bottom
Y6  25MEGHZ  [YSML98W79H35]  14.38 25.21 180 bottom

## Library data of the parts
C1-C3 C5-C8 C37 C42 C47 C62 C67 C68 C72 C73 C75 C77 C78 C82 C83 C87-C89 C91 C93 C96 C98 C100 C104 C112 C118 C122 C134 C138 C142 C153 C156 C170-C172 C202 C215 C218 C229 C234-C243 C248-C253 = CAP: User Part Number: UPN; Tolerance: 10; alternate symbols: (C0402L); part number: CAP_SM-0.1UF,25V,10,E033331,C0402; tolerance: 10
C4 = CAP: User Part Number: UPN; Tolerance: 5; alternate symbols: (C0402L); part number: CAP_SM-100PF,50V,5,E024302,C0402; tolerance: 5
C9 C10 C12 C14 C16 C18 C21 C23 C25 C29 C31 C33 C35 C64 C70 C80 C85 C86 C92 C97 C101 C105 C107 C108 C113 C117 C121 C125 C127 C128 C132 C136 C137 C141 C145 C147 C149 C152 C245-C247 = CAP: Tolerance: 10; User Part Number: UPN; alternate symbols: (C0201L); part number: CAP_SM-0.01UF,10V,10,E041205,C0201; tolerance: 10
C11 C13 C22 C24 C26 C49 C50 C52 C54 C55 C57 = CAP: User Part Number: UPN; Tolerance: 10; alternate symbols: (); part number: CAP_SM-10UF,16V,10,E040074,C0805H55; tolerance: 10
C15 C17 = CAP: Tolerance: 10; User Part Number: UPN; alternate symbols: (C1206H71L); part number: CAP_SM-4.7UF,50V,10,E033298,C1206H71; tolerance: 10
C19 C20 = CAP: Tolerance: 20; User Part Number: UPN; alternate symbols: (); part number: CAP_SM-100UF,6.3V,20,E034669,C1210H106; tolerance: 20
C27 C41 C43 C48 C51 C53 C56 C61 C66 C232 C233 C254 = CAP: User Part Number: UPN; Tolerance: 10; alternate symbols: (C0402L); part number: CAP_SM-1UF,10V,10,E028140,C0402; tolerance: 10
C28 C32 C46 C173-C176 C179-C182 C184 C188 C189 C244 = CAP: User Part Number: UPN; Tolerance: 10; alternate symbols: (C0402L); part number: CAP_SM-0.01UF,25V,10,E030894,C0402; tolerance: 10
C30 C34 C36 C39 C40 C45 C109 C129 C133 C178 C183 C186 C187 = CAP: User Part Number: UPN; Tolerance: 10; alternate symbols: (C0402L); part number: CAP_SM-0.1UF,16V,10,E028141,C0402; tolerance: 10
C38 C185 = CAP: User Part Number: UPN; Tolerance: 10; alternate symbols: (C0603L); part number: CAP_SM-4.7UF,10V,10,E034981,C0603; tolerance: 10
C44 C177 = CAP: User Part Number: UPN; Tolerance: 20; alternate symbols: (C0603L); part number: CAP_SM-10UF,10V,20,E033351,C0603; tolerance: 20
C58 C60 C63 C65 C69 C71 C74 C76 C79 C81 C84 C106 C123 C126 C131 C135 C139 C143 C146 C151 C154 C157 C163 = CAP: User Part Number: UPN; Tolerance: 10; alternate symbols: (C0402L); part number: CAP_SM-0.22UF,25V,10,E041210,C0402; tolerance: 10
C59 C90 C95 C99 C103 C110 C111 C114-C116 C119 C120 C124 C130 C140 C144 C148 C150 C155 C161 C164 C165 = CAP: User Part Number: UPN; Tolerance: 10; alternate symbols: (C0402L); part number: CAP_SM-0.47UF,10V,10,E035987,C0402; tolerance: 10
C94 C102 C162 = CAP: User Part Number: UPN; Tolerance: 5; alternate symbols: (C0603L); part number: CAP_SM-1000PF,200V,5,E012699,C0603; tolerance: 5
C158 = CAP: User Part Number: UPN; Tolerance: 10; alternate symbols: (C0603L); part number: CAP_SM-4.7UF,35V,10,E039350,C0603; tolerance: 10
C159 C199-C201 = CAP: User Part Number: UPN; Tolerance: -20%, +80%; alternate symbols: (C0603L); part number: CAP_SM-1UF,10V,-20%, +80%,E017857,C0603; tolerance: -20%, +80%
C160 = CAP: User Part Number: UPN; Tolerance: 10; alternate symbols: (C0402L); part number: CAP_SM-0.1UF,16V,10,E033898,C0402; tolerance: 10
C166-C169 = CAP: User Part Number: UPN; Tolerance: 5; alternate symbols: (C0402L); part number: CAP_SM-27PF,50V,5,E033384,C0402; tolerance: 5
C190 C203 C205 = CAP: Tolerance: 10; User Part Number: UPN; alternate symbols: (); part number: CAP_SM-10UF,50V,10,E033329,C1210-2; tolerance: 10
C191 C192 = CAP: User Part Number: UPN; Tolerance: 10; alternate symbols: (C0402L); part number: CAP_SM-0.22UF,16V,10,E035311,C0402; tolerance: 10
C193 = CAP: User Part Number: UPN; Tolerance: 0.05pF; alternate symbols: (C0402L); part number: CAP_SM-3.3PF,50V,0.05PF,E040139,C0402; tolerance: 0.05pF
C194 C197 C224 C227 C230 = CAP: Tolerance: 10; User Part Number: UPN; alternate symbols: (); part number: CAP_SM-22UF,10V,10,E030857,C1206H71; tolerance: 10
C195 = CAP: User Part Number: UPN; Tolerance: 10; alternate symbols: (C0402L); part number: CAP_SM-270PF,50V,10,E040140,C0402; tolerance: 10
C196 C198 C206 C212 C228 = CAP: Tolerance: 10; User Part Number: UPN; alternate symbols: (); part number: CAP_SM-1UF,100V,10,E044891,C1206H71; tolerance: 10
C204 = CAP: User Part Number: UPN; Tolerance: 10; alternate symbols: (C0402L); part number: CAP_SM-1500PF,50V,10,E034252,C0402; tolerance: 10
C207 = CAP: User Part Number: UPN; Tolerance: 10; alternate symbols: (C0603L); part number: CAP_SM-0.1UF,25V,10,E031923,C0603; tolerance: 10
C208 C209 = CAP: User Part Number: UPN; Tolerance: 1; alternate symbols: (C0402L); part number: CAP_SM-100PF,50V,1,E033808,C0402; tolerance: 1
C210 = CAP: User Part Number: UPN; Tolerance: 5; alternate symbols: (C0402L); part number: CAP_SM-47PF,50V,5,E011821,C0402; tolerance: 5
C211 C213 C214 C216 C217 C219 C221 C223 C226 = CAP: Tolerance: 10; User Part Number: UPN; alternate symbols: (); part number: CAP_SM-47UF,25V,10,E038014,C1210H95; tolerance: 10
C220 = CAP: User Part Number: UPN; Tolerance: 0.25; alternate symbols: (C0402L); part number: CAP_SM-2.2PF,50V,0.25,E040073,C0402; tolerance: 0.25
C222 C225 C231 = CAP: Tolerance: 10; User Part Number: UPN; alternate symbols: (); part number: CAP_SM-4.7UF,35V,10,E026260,C0805H60; tolerance: 10
D1 = DIOTVS6P_V9: User Part Number: UPN; Tolerance: N/A; alternate symbols: (); part number: DIOTVS6P_V9_SM-ESDA6V1SC6Y,5.2V,N/A,E040427,SOT23_6-3; tolerance: N/A
D2 = DIO10P_V3: User Part Number: UPN; Tolerance: N/A; alternate symbols: (); part number: DIO10P_V3_SM-SZESD7004MUTAG,N/A,N/A,E040100,UDFN10_2_5X1; tolerance: N/A
D15 D18 = DIOZNR: User Part Number: UPN; Tolerance: N/A; alternate symbols: (); part number: DIOZNR_SM-ESDA25P35-1U1M,22V,N/A,E045024,DFN2_1_6X1; tolerance: N/A
D16 = DIOSCHOTTKY: User Part Number: UPN; Tolerance: N/A; alternate symbols: (); part number: DIOSCHOTTKY_SM-NRVTSA3100ET3G,100V,N/A,E044405,SMA; tolerance: N/A
D17 = DIOTVS5P_V4: User Part Number: UPN; Tolerance: N/A; alternate symbols: (); part number: DIOTVS5P_V4_SM-ESDA25W5,24V,N/A,E045025,SC70-5_A; tolerance: N/A
DS1-DS4 = DIOLED: Tolerance: N/A; User Part Number: UPN; alternate symbols: (); part number: DIOLED_SM-SML-D13FWT86C,2.1V,N/A,E040424,LED0603-2; tolerance: N/A
DS5 DS6 = DIOLED: User Part Number: UPN; Tolerance: N/A; alternate symbols: (); part number: DIOLED_SM-SML-D14U2WT86C,2V,N/A,E040428,LED0603_A; tolerance: N/A
DS7 DS8 = DIOLED: Tolerance: N/A; User Part Number: UPN; alternate symbols: (); part number: DIOLED_SM-LY L296-Q2R2-26-Z,2V,N/A,E027232,LED0603-2; tolerance: N/A
E1 = FERRITE: Tolerance: 25; User Part Number: UPN; alternate symbols: (L1206L); part number: FERRITE_SM-600OHM,25,E019012,L1206; tolerance: 25
FL1 FL2 = FLTR3P: Tolerance: -4; User Part Number: UPN; alternate symbols: (); part number: FLTR3P_SM-4700PF,E011145,F2606; tolerance: -4
J1-J3 = CN100P_V2: Tolerance: N/A; User Part Number: UPN; alternate symbols: (); part number: CN100P_V2_SM-A-LSS-150-01-L-DV-A-K,E041063,CNSAMTECLSS-150-01-X-DV-A; tolerance: N/A
JP1 = CN3P: User Part Number: UPN; Tolerance: N/A; alternate symbols: (); part number: CN3P_SM-TSM-103-01-H-SV,E044652,CNSMMHDR1X3L300W100H403; tolerance: N/A
L1 = IND: User Part Number: UPN; Tolerance: 20; alternate symbols: (); part number: IND_SM-10UH,20,E028516,L1210H67; tolerance: 20
L2 = IND: User Part Number: UPN; Tolerance: 20; alternate symbols: (); part number: IND_SM-0.1UH,20,E046177,LSMSQ157H122; tolerance: 20
L3 = IND: Tolerance: 20; User Part Number: UPN; alternate symbols: (); part number: IND_SM-1UH,20,E018077,LSML208W216H122; tolerance: 20
L4 = IND: User Part Number: UPN; Tolerance: 20; alternate symbols: (); part number: IND_SM-220NH,20,E032809,LSMSQ157H83_A; tolerance: 20
P1 = CN24PAB_2GND_6SHLD: Tolerance: N/A; User Part Number: UPN; alternate symbols: (); part number: CN24PAB_2GND_6SHLD_TH-632723300011,E043638,CNWURTH632723300011; tolerance: N/A
P6 = CN10P_ODD_EVEN: User Part Number: UPN; Tolerance: N/A; alternate symbols: (); part number: CN10P_ODD_EVEN_TH-SHF-105-01-L-D-TH-TR,E027236,CNTHMHDR2X5L500W200H215; tolerance: N/A
Q4 Q5 = TRANPMOSFET_V9: User Part Number: UPN; Tolerance: N/A; alternate symbols: (); part number: TRANPMOSFET_V9_SM-STL6P3LLH6,E044541,POWERFLAT_33X33; tolerance: N/A
R1 = RES: User Part Number: UPN; Tolerance: 1; alternate symbols: (R0402L); part number: RES_SM-34,E040037,1/10W,1,R0402; tolerance: 1
R2 = RES: User Part Number: UPN; Tolerance: 1; alternate symbols: (R0402L,R0402L_ALT); part number: RES_SM-2K,E003752,1/10W,1,R0402; tolerance: 1
R3 = RES: User Part Number: UPN; Tolerance: 0.5; alternate symbols: (R0402L); part number: RES_SM-200,E022007,1/16W,0.5,R0402; tolerance: 0.5
R4 = RES: User Part Number: UPN; Tolerance: 1; alternate symbols: (R0402L,R0402L_ALT); part number: RES_SM-240,E010877,1/10W,1,R0402; tolerance: 1
R5 R7 R16 R18 R19 R27-R29 R32-R45 R58 R85 R88 R111 R112 R141 R142 R144 = RES: User Part Number: UPN; Tolerance: JUMPER; alternate symbols: (R0402L); part number: RES_SM-0,E030866,1/5W,JUMPER,R0402; tolerance: JUMPER
R6 R66 = RES: User Part Number: UPN; Tolerance: 0.1; alternate symbols: (R0402L); part number: RES_SM-5.1K,E010267,1/16W,0.1,R0402; tolerance: 0.1
R8 R24-R26 R46-R48 R50 R51 R57 R60-R63 R68 R70 R71 R75 R78 R79 R86 R87 R118-R122 R131-R135 R138-R140 R143 = RES: User Part Number: UPN; Tolerance: 1; alternate symbols: (R0402L,R0402L_ALT); part number: RES_SM-10K,E003751,1/10W,1,R0402; tolerance: 1
R9-R11 R146 = RES: User Part Number: UPN; Tolerance: 1; alternate symbols: (R0402L,R0402L_ALT); part number: RES_SM-1K,E003763,1/10W,1,R0402; tolerance: 1
R12 R13 R65 = RES: User Part Number: UPN; Tolerance: 1; alternate symbols: (R0402L); part number: RES_SM-100,E016329,1/10W,1,R0402; tolerance: 1
R14 R15 = RES: User Part Number: UPN; Tolerance: 5; alternate symbols: (R0402L); part number: RES_SM-2.2K,E003446,1/10W,5,R0402; tolerance: 5
R17 = RES: User Part Number: UPN; Tolerance: 1; alternate symbols: (R0402L); part number: RES_SM-20,E020520,1/10W,1,R0402; tolerance: 1
R20 R21 = RES: User Part Number: UPN; Tolerance: 1; alternate symbols: (R0402L,R0402L_ALT); part number: RES_SM-1.2K,E007439,1/10W,1,R0402; tolerance: 1
R22 R23 = RES: User Part Number: UPN; Tolerance: 1; alternate symbols: (R0402L); part number: RES_SM-499K,E019889,1/10W,1,R0402; tolerance: 1
R30 = RES: User Part Number: UPN; Tolerance: 1; alternate symbols: (R0402L); part number: RES_SM-3.01K,E027299,1/10W,1,R0402; tolerance: 1
R31 R64 = RES: User Part Number: UPN; Tolerance: 1; alternate symbols: (R0402L); part number: RES_SM-1.5K,E003782,1/10W,1,R0402; tolerance: 1
R49 R52 R110 = RES: User Part Number: UPN; Tolerance: 5; alternate symbols: (R0402L); part number: RES_SM-33,E003452,1/10W,5,R0402; tolerance: 5
R53-R56 R81-R84 R114-R117 R125-R128 = RES: User Part Number: UPN; Tolerance: 5; alternate symbols: (R0402L); part number: RES_SM-100K,E027220,1/16W,5,R0402; tolerance: 5
R59 R72-R74 R76 R77 R89 R90 = RES: User Part Number: UPN; Tolerance: 1; alternate symbols: (R0402L,R0402L_ALT); part number: RES_SM-330,E021894,1/16W,1,R0402; tolerance: 1
R67 = RES: User Part Number: UPN; Tolerance: 5; alternate symbols: (R1206L); part number: RES_SM-0,E010093,1/4W,5,R1206; tolerance: 5
R80 = RES: User Part Number: UPN; Tolerance: 1; alternate symbols: (R0603L); part number: RES_SM-1MEG,E030873,1/10W,1,R0603; tolerance: 1
R91 = RES: User Part Number: UPN; Tolerance: 1; alternate symbols: (R0402L); part number: RES_SM-37.4K,E017173,1/10W,1,R0402; tolerance: 1
R92-R94 = RES: User Part Number: UPN; Tolerance: JUMPER; alternate symbols: (R0402L,R0402L_ALT); part number: RES_SM-0,E003438,1/10W,JUMPER,R0402; tolerance: JUMPER
R95 = RES: User Part Number: UPN; Tolerance: 1; alternate symbols: (R0402L); part number: RES_SM-38.3K,E016739,1/10W,1,R0402; tolerance: 1
R96 R99-R101 R104 R105 R107 R108 = RES: User Part Number: UPN; Tolerance: 1; alternate symbols: (R0402L,R0402L_ALT); part number: RES_SM-100K,E003796,1/10W,1,R0402; tolerance: 1
R97 = RES: User Part Number: UPN; Tolerance: 1; alternate symbols: (R0402L); part number: RES_SM-1.69MEG,E038133,1/16W,1,R0402; tolerance: 1
R98 = RES: User Part Number: UPN; Tolerance: 0.1; alternate symbols: (R0402L); part number: RES_SM-15.8K,E023709,1/16W,0.1,R0402; tolerance: 0.1
R102 = RES: User Part Number: UPN; Tolerance: 0.1; alternate symbols: (R0402L); part number: RES_SM-91K,E041184,1/16W,0.1,R0402; tolerance: 0.1
R103 = RES: User Part Number: UPN; Tolerance: 0.1; alternate symbols: (R0805L); part number: RES_SM-9K,E029209,1/8W,0.1,R0805; tolerance: 0.1
R106 = RES: User Part Number: UPN; Tolerance: 1; alternate symbols: (R0402L); part number: RES_SM-41.2K,E022008,1/10W,1,R0402; tolerance: 1
R109 = RES: User Part Number: UPN; Tolerance: 1; alternate symbols: (R0402L); part number: RES_SM-56.2K,E003771,1/10W,1,R0402; tolerance: 1
R113 = RES: User Part Number: UPN; Tolerance: 1; alternate symbols: (R0402L); part number: RES_SM-6.98K,E026014,1/10W,1,R0402; tolerance: 1
R123 = RES: User Part Number: UPN; Tolerance: 1; alternate symbols: (R0402L); part number: RES_SM-470,E042472,1/10W,1,R0402; tolerance: 1
R124 = RES: User Part Number: UPN; Tolerance: 5; alternate symbols: (R0402L); part number: RES_SM-1K,E020936,1/16W,5,R0402; tolerance: 5
R129 = RES: User Part Number: UPN; Tolerance: 1; alternate symbols: (R0402L); part number: RES_SM-22K,E018369,1/16W,1,R0402; tolerance: 1
R130 = RES: User Part Number: UPN; Tolerance: 1; alternate symbols: (R0402L,R0402L_ALT); part number: RES_SM-100,E003760,1/16W,1,R0402; tolerance: 1
R136 R137 = RES: User Part Number: UPN; Tolerance: 1; alternate symbols: (R0402L,R0402L_ALT); part number: RES_SM-3.3K,E010034,1/10W,1,R0402; tolerance: 1
RN1-RN7 = RESNET_8P_4R_V4: Tolerance: 5; User Part Number: UPN; alternate symbols: (); part number: RESNET_8P_4R_V4_SM-100,E046239,0.063W,5,RESNET8; tolerance: 5
S1 = SWBCDROTARY6P: User Part Number: UPN; Tolerance: N/A; alternate symbols: (); part number: SWBCDROTARY6P_SM-RDTAR10S1R,E040089,SWSMSQ394H268; tolerance: N/A
S2 = SWSPST4PIN_V6: Tolerance: N/A; User Part Number: UPN; alternate symbols: (); part number: SWSPST4PIN_V6_SM-KMR223GLFG,E040082,SWSML165W110H75; tolerance: N/A
TP1-TP4 = CNTP1P: User Part Number: UPN; Tolerance: N/A; alternate symbols: (); part number: CNTP1P_TH-WHT,E000946,CNLOOPTP; tolerance: N/A
U1 = ADSP_SC59X: User Part Number: UPN; Tolerance: N/A; alternate symbols: (); part number: ADSP_SC59X_SM-ADSP-SC598-BPZENG,E049100,CSPBGA400_17X17; tolerance: N/A
U2 = ICMIC5166: Tolerance: N/A; User Part Number: UPN; alternate symbols: (); part number: ICMIC5166_SM-MIC5166YML-TR,E050642,DFN10_3X3_PAD2_4X1_7; tolerance: N/A
U3 = ICSI5356X: User Part Number: UPN; Tolerance: N/A; alternate symbols: (); part number: ICSI5356X_SM-SI5356A-B03215-GM,E041435,QFN24_4X4_PAD2_5X2_5; tolerance: N/A
U4 = ICIS25LP512: Tolerance: N/A; User Part Number: UPN; alternate symbols: (); part number: ICIS25LP512_SM-IS25LP512M-RMLA3,E040080,SO16WB; tolerance: N/A
U5 U9 U10 = 741G125: User Part Number: UPN; Tolerance: N/A; alternate symbols: (); part number: 741G125_SM-74CBTLV1G125DBVRQ1,E040081,SOT23-5L-2; tolerance: N/A
U6 = ICSTUSB4500: Tolerance: N/A; User Part Number: UPN; alternate symbols: (); part number: ICSTUSB4500_SM-STUSB4500QTR,E044542,QFN24_4X4_PAD2_7X2_7; tolerance: N/A
U7 = CMOSPI3C3125: Tolerance: N/A; User Part Number: UPN; alternate symbols: (); part number: CMOSPI3C3125_SM-PI3C3125LEX,E040333,TSSOP14; tolerance: N/A
U8 = ICIS4XTR16256: User Part Number: UPN; Tolerance: N/A; alternate symbols: (); part number: ICIS4XTR16256_SM-IS43TR16256BL-107MBL,E057159,BGA96_13X9; tolerance: N/A
U11 U13 = 7408_V3: User Part Number: UPN; Tolerance: N/A; alternate symbols: (); part number: 7408_V3_SM-SN74LVC1G08QDBVRQ1,E040048,SOT23-5L-2; tolerance: N/A
U12 U20-U23 U25 = CMOSSN74CB3T3125: Tolerance: N/A; User Part Number: UPN; alternate symbols: (); part number: CMOSSN74CB3T3125_SM-SN74CB3T3125RGYR,E050248,QFN14_3_5X3_5_PAD2_05X2_05; tolerance: N/A
U14 = ADM6315: User Part Number: UPN; Tolerance: N/A; alternate symbols: (); part number: ADM6315_SM-ADM6315-29D2ARTZR7,E027659,SOT143A; tolerance: N/A
U15 = ICFT232RQ: User Part Number: UPN; Tolerance: N/A; alternate symbols: (); part number: ICFT232RQ_SM-FT232RQ,E018265,QFN32_5X5_PAD3_2X3_2; tolerance: N/A
U16 = ADLTC3310: User Part Number: UPN; Tolerance: N/A; alternate symbols: (); part number: ADLTC3310_SM-LTC3310JV#WPBF,E045269,QFN18_3X3_PAD1_51X1_7; tolerance: N/A
U17 = ADLTC3307: User Part Number: UPN; Tolerance: N/A; alternate symbols: (); part number: ADLTC3307_SM-LTC3307AHV#WTRMPBF,E042057,QFN12_2X2_PAD0_7X0_7; tolerance: N/A
U18 = ADP120_V2: User Part Number: UPN; Tolerance: N/A; alternate symbols: (); part number: ADP120_V2_SM-ADP151AUJZ-1.8-R7,E013337,TSOT-5; tolerance: N/A
U19 = ICIS2XES04G: User Part Number: UPN; Tolerance: N/A; alternate symbols: (); part number: ICIS2XES04G_SM-IS21ES04G,E049414,BGA153_13X11_50; tolerance: N/A
U24 = ICMC23018: User Part Number: UPN; Tolerance: N/A; alternate symbols: (); part number: ICMC23018_SM-MCP23018-E/MJ,E030235,QFN24_4X4_PAD2_5X2_5; tolerance: N/A
U26 = IC24XX01: User Part Number: UPN; Tolerance: N/A; alternate symbols: (); part number: IC24XX01_SM-24AA01T-I/OT,E035648,SOT23-5L-2; tolerance: N/A
VR1 = ADLT8636: User Part Number: UPN; Tolerance: N/A; alternate symbols: (); part number: ADLT8636_SM-LT8636EV#WPBF,E041170,LQFN20_4X3_PAD2_65X1_65; tolerance: N/A
Y1-Y3 = XTAL4PIN_V5: Tolerance: 20PPM; User Part Number: UPN; alternate symbols: (); part number: XTAL4PIN_V5_SM-25MEGHZ,E050382,YSML126W98H31; tolerance: 20PPM
Y4 = XTALOSC4P_V18: Tolerance: N/A; User Part Number: UPN; alternate symbols: (); part number: XTALOSC4P_V18_SM-24.576MEGHZ,E049327,YSML79W63H31; tolerance: N/A
Y5 Y6 = XTALOSC4P_V2: Tolerance: N/A; User Part Number: UPN; alternate symbols: (); part number: XTALOSC4P_V2_SM-25MEGHZ,E032840,YSML98W79H35; tolerance: N/A

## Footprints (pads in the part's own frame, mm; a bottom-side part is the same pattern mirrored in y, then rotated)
BGA96_13X9
  round 0.356 smd: A1(-6,-3.2) A2(-6,-2.4) A3(-6,-1.6) A7(-6,1.6) A8(-6,2.4) A9(-6,3.2) B1(-5.2,-3.2) B2(-5.2,-2.4) B3(-5.2,-1.6) B7(-5.2,1.6) B8(-5.2,2.4) B9(-5.2,3.2) C1(-4.4,-3.2) C2(-4.4,-2.4) C3(-4.4,-1.6) C7(-4.4,1.6) C8(-4.4,2.4) C9(-4.4,3.2) D1(-3.6,-3.2) D2(-3.6,-2.4) D3(-3.6,-1.6) D7(-3.6,1.6) D8(-3.6,2.4) D9(-3.6,3.2) E1(-2.8,-3.2) E2(-2.8,-2.4) E3(-2.8,-1.6) E7(-2.8,1.6) E8(-2.8,2.4) E9(-2.8,3.2) F1(-2,-3.2) F2(-2,-2.4) F3(-2,-1.6) F7(-2,1.6) F8(-2,2.4) F9(-2,3.2) G1(-1.2,-3.2) G2(-1.2,-2.4) G3(-1.2,-1.6) G7(-1.2,1.6) G8(-1.2,2.4) G9(-1.2,3.2) H1(-0.4,-3.2) H2(-0.4,-2.4) H3(-0.4,-1.6) H7(-0.4,1.6) H8(-0.4,2.4) H9(-0.4,3.2) J1(0.4,-3.2) J2(0.4,-2.4) J3(0.4,-1.6) J7(0.4,1.6) J8(0.4,2.4) J9(0.4,3.2) K1(1.2,-3.2) K2(1.2,-2.4) K3(1.2,-1.6) K7(1.2,1.6) K8(1.2,2.4) K9(1.2,3.2) L1(2,-3.2) L2(2,-2.4) L3(2,-1.6) L7(2,1.6) L8(2,2.4) L9(2,3.2) M1(2.8,-3.2) M2(2.8,-2.4) M3(2.8,-1.6) M7(2.8,1.6) M8(2.8,2.4) M9(2.8,3.2) N1(3.6,-3.2) N2(3.6,-2.4) N3(3.6,-1.6) N7(3.6,1.6) N8(3.6,2.4) N9(3.6,3.2) P1(4.4,-3.2) P2(4.4,-2.4) P3(4.4,-1.6) P7(4.4,1.6) P8(4.4,2.4) P9(4.4,3.2) R1(5.2,-3.2) R2(5.2,-2.4) R3(5.2,-1.6) R7(5.2,1.6) R8(5.2,2.4) R9(5.2,3.2) T1(6,-3.2) T2(6,-2.4) T3(6,-1.6) T7(6,1.6) T8(6,2.4) T9(6,3.2)
BGA153_13X11_50
  round 0.229 smd: A1(-3.25,-3.25) A2(-3.25,-2.75) A3(-3.25,-2.25) A4(-3.25,-1.75) A5(-3.25,-1.25) A6(-3.25,-0.75) A7(-3.25,-0.25) A8(-3.25,0.25) A9(-3.25,0.75) A10(-3.25,1.25) A11(-3.25,1.75) A12(-3.25,2.25) A13(-3.25,2.75) A14(-3.25,3.25) B1(-2.75,-3.25) B2(-2.75,-2.75) B3(-2.75,-2.25) B4(-2.75,-1.75) B5(-2.75,-1.25) B6(-2.75,-0.75) B7(-2.75,-0.25) B8(-2.75,0.25) B9(-2.75,0.75) B10(-2.75,1.25) B11(-2.75,1.75) B12(-2.75,2.25) B13(-2.75,2.75) B14(-2.75,3.25) C1(-2.25,-3.25) C2(-2.25,-2.75) C3(-2.25,-2.25) C4(-2.25,-1.75) C5(-2.25,-1.25) C6(-2.25,-0.75) C7(-2.25,-0.25) C8(-2.25,0.25) C9(-2.25,0.75) C10(-2.25,1.25) C11(-2.25,1.75) C12(-2.25,2.25) C13(-2.25,2.75) C14(-2.25,3.25) D1(-1.75,-3.25) D2(-1.75,-2.75) D3(-1.75,-2.25) D4(-1.75,-1.75) D12(-1.75,2.25) D13(-1.75,2.75) D14(-1.75,3.25) E1(-1.25,-3.25) E2(-1.25,-2.75) E3(-1.25,-2.25) E5(-1.25,-1.25) E6(-1.25,-0.75) E7(-1.25,-0.25) E8(-1.25,0.25) E9(-1.25,0.75) E10(-1.25,1.25) E12(-1.25,2.25) E13(-1.25,2.75) E14(-1.25,3.25) F1(-0.75,-3.25) F2(-0.75,-2.75) F3(-0.75,-2.25) F5(-0.75,-1.25) F10(-0.75,1.25) F12(-0.75,2.25) F13(-0.75,2.75) F14(-0.75,3.25) G1(-0.25,-3.25) G2(-0.25,-2.75) G3(-0.25,-2.25) G5(-0.25,-1.25) G10(-0.25,1.25) G12(-0.25,2.25) G13(-0.25,2.75) G14(-0.25,3.25) H1(0.25,-3.25) H2(0.25,-2.75) H3(0.25,-2.25) H5(0.25,-1.25) H10(0.25,1.25) H12(0.25,2.25) H13(0.25,2.75) H14(0.25,3.25) J1(0.75,-3.25) J2(0.75,-2.75) J3(0.75,-2.25) J5(0.75,-1.25) J10(0.75,1.25) J12(0.75,2.25) J13(0.75,2.75) J14(0.75,3.25) K1(1.25,-3.25) K2(1.25,-2.75) K3(1.25,-2.25) K5(1.25,-1.25) K6(1.25,-0.75) K7(1.25,-0.25) K8(1.25,0.25) K9(1.25,0.75) K10(1.25,1.25) K12(1.25,2.25) K13(1.25,2.75) K14(1.25,3.25) L1(1.75,-3.25) L2(1.75,-2.75) L3(1.75,-2.25) L12(1.75,2.25) L13(1.75,2.75) L14(1.75,3.25) M1(2.25,-3.25) M2(2.25,-2.75) M3(2.25,-2.25) M4(2.25,-1.75) M5(2.25,-1.25) M6(2.25,-0.75) M7(2.25,-0.25) M8(2.25,0.25) M9(2.25,0.75) M10(2.25,1.25) M11(2.25,1.75) M12(2.25,2.25) M13(2.25,2.75) M14(2.25,3.25) N1(2.75,-3.25) N2(2.75,-2.75) N3(2.75,-2.25) N4(2.75,-1.75) N5(2.75,-1.25) N6(2.75,-0.75) N7(2.75,-0.25) N8(2.75,0.25) N9(2.75,0.75) N10(2.75,1.25) N11(2.75,1.75) N12(2.75,2.25) N13(2.75,2.75) N14(2.75,3.25) P1(3.25,-3.25) P2(3.25,-2.75) P3(3.25,-2.25) P4(3.25,-1.75) P5(3.25,-1.25) P6(3.25,-0.75) P7(3.25,-0.25) P8(3.25,0.25) P9(3.25,0.75) P10(3.25,1.25) P11(3.25,1.75) P12(3.25,2.25) P13(3.25,2.75) P14(3.25,3.25)
C0201
  rect 0.305x0.406 smd: 1(-0.318,0) 2(0.318,0)
C0402
  rect 0.584x0.66 smd: 1(-0.5,0) 2(0.5,0)
C0603
  rect 0.94x0.991 smd: 1(-0.8,0) 2(0.8,0)
C0805H55
  rect 1.143x1.448 smd: 1(-0.9,0) 2(0.9,0)
C0805H60
  rect 1.295x1.6 smd: 1(-0.953,0) 2(0.953,0)
C1206H71
  rect 1.6x2.007 smd: 1(-1.397,0) 2(1.397,0)
C1210-2
  rect 1.575x2.692 smd: 1(-1.397,0) 2(1.397,0)
C1210H95
  rect 1.575x2.692 smd: 1(-1.397,0) 2(1.397,0)
C1210H106
  rect 1.092x2.057 smd: 1(-1.646,0) 2(1.646,0)
CNLOOPTP
  round 2.159 hole 1.6: 1(0,0)
CNSAMTECLSS-150-01-X-DV-A
  round 1.016 hole 0.889 unplated: (-16.625,-1.1) (16.625,-1.1)
  rect 0.406x1.6 smd: 1(-15.557,1.8) 2(-15.557,-1.8) 3(-14.922,1.8) 4(-14.922,-1.8) 5(-14.287,1.8) 6(-14.287,-1.8) 7(-13.652,1.8) 8(-13.652,-1.8) 9(-13.018,1.8) 10(-13.018,-1.8) 11(-12.383,1.8) 12(-12.383,-1.8) 13(-11.748,1.8) 14(-11.748,-1.8) 15(-11.113,1.8) 16(-11.113,-1.8) 17(-10.477,1.8) 18(-10.477,-1.8) 19(-9.842,1.8) 20(-9.842,-1.8) 21(-9.207,1.8) 22(-9.207,-1.8) 23(-8.572,1.8) 24(-8.572,-1.8) 25(-7.938,1.8) 26(-7.938,-1.8) 27(-7.303,1.8) 28(-7.303,-1.8) 29(-6.668,1.8) 30(-6.668,-1.8) 31(-6.032,1.8) 32(-6.032,-1.8) 33(-5.397,1.8) 34(-5.397,-1.8) 35(-4.763,1.8) 36(-4.763,-1.8) 37(-4.128,1.8) 38(-4.128,-1.8) 39(-3.493,1.8) 40(-3.493,-1.8) 41(-2.857,1.8) 42(-2.857,-1.8) 43(-2.223,1.8) 44(-2.223,-1.8) 45(-1.587,1.8) 46(-1.587,-1.8) 47(-0.953,1.8) 48(-0.953,-1.8) 49(-0.318,1.8) 50(-0.318,-1.8) 51(0.318,1.8) 52(0.318,-1.8) 53(0.953,1.8) 54(0.953,-1.8) 55(1.587,1.8) 56(1.587,-1.8) 57(2.223,1.8) 58(2.223,-1.8) 59(2.857,1.8) 60(2.857,-1.8) 61(3.493,1.8) 62(3.493,-1.8) 63(4.128,1.8) 64(4.128,-1.8) 65(4.763,1.8) 66(4.763,-1.8) 67(5.397,1.8) 68(5.397,-1.8) 69(6.032,1.8) 70(6.032,-1.8) 71(6.668,1.8) 72(6.668,-1.8) 73(7.303,1.8) 74(7.303,-1.8) 75(7.938,1.8) 76(7.938,-1.8) 77(8.572,1.8) 78(8.572,-1.8) 79(9.207,1.8) 80(9.207,-1.8) 81(9.842,1.8) 82(9.842,-1.8) 83(10.477,1.8) 84(10.477,-1.8) 85(11.113,1.8) 86(11.113,-1.8) 87(11.748,1.8) 88(11.748,-1.8) 89(12.383,1.8) 90(12.383,-1.8) 91(13.018,1.8) 92(13.018,-1.8) 93(13.652,1.8) 94(13.652,-1.8) 95(14.287,1.8) 96(14.287,-1.8) 97(14.922,1.8) 98(14.922,-1.8) 99(15.557,1.8) 100(15.557,-1.8)
CNSMMHDR1X3L300W100H403
  rect 1.27x3.429 smd: 1(-2.54,1.46) 2(0,-1.46) 3(2.54,1.46)
CNTHMHDR2X5L500W200H215
  rect 1.143x1.143 hole 0.737: 1(0,0)
  round 1.143 hole 0.737: 2(0,1.27) 3(1.27,0) 4(1.27,1.27) 5(2.54,0) 6(2.54,1.27) 7(3.81,0) 8(3.81,1.27) 9(5.08,0) 10(5.08,1.27)
CNWURTH632723300011
  rect 0.305x1.194 smd: A1(-2.75,4.577) A2(-2.25,4.577) A3(-1.75,4.577) A4(-1.25,4.577) A5(-0.75,4.577) A6(-0.25,4.577) A7(0.25,4.577) A8(0.75,4.577) A9(1.25,4.577) A10(1.75,4.577) A11(2.25,4.577) A12(2.75,4.577)
  round 0.66 hole 0.406: B1(2.8,3.33) B2(2.4,2.63) B3(1.6,2.63) B4(1.2,3.33) B5(0.8,2.63) B6(0.4,3.33) B7(-0.4,3.33) B8(-0.8,2.63) B9(-1.2,3.33) B10(-1.6,2.63) B11(-2.4,2.63) B12(-2.8,3.33) GND1(-2,3.33) GND2(2,3.33)
  oval 0.991x1.6 hole 0.61x1.219: SH1(-4.27,2.18) SH2(4.27,2.18) SH3(4.27,-2.55) SH4(-4.27,-2.55)
  rect 0.203x0.991 smd: SH5(0,-0.005) SH6(0,-3.105)
CSPBGA400_17X17
  round 0.356 smd: A1(-7.6,-7.6) A2(-7.6,-6.8) A3(-7.6,-6) A4(-7.6,-5.2) A5(-7.6,-4.4) A6(-7.6,-3.6) A7(-7.6,-2.8) A8(-7.6,-2) A9(-7.6,-1.2) A10(-7.6,-0.4) A11(-7.6,0.4) A12(-7.6,1.2) A13(-7.6,2) A14(-7.6,2.8) A15(-7.6,3.6) A16(-7.6,4.4) A17(-7.6,5.2) A18(-7.6,6) A19(-7.6,6.8) A20(-7.6,7.6) B1(-6.8,-7.6) B2(-6.8,-6.8) B3(-6.8,-6) B4(-6.8,-5.2) B5(-6.8,-4.4) B6(-6.8,-3.6) B7(-6.8,-2.8) B8(-6.8,-2) B9(-6.8,-1.2) B10(-6.8,-0.4) B11(-6.8,0.4) B12(-6.8,1.2) B13(-6.8,2) B14(-6.8,2.8) B15(-6.8,3.6) B16(-6.8,4.4) B17(-6.8,5.2) B18(-6.8,6) B19(-6.8,6.8) B20(-6.8,7.6) C1(-6,-7.6) C2(-6,-6.8) C3(-6,-6) C4(-6,-5.2) C5(-6,-4.4) C6(-6,-3.6) C7(-6,-2.8) C8(-6,-2) C9(-6,-1.2) C10(-6,-0.4) C11(-6,0.4) C12(-6,1.2) C13(-6,2) C14(-6,2.8) C15(-6,3.6) C16(-6,4.4) C17(-6,5.2) C18(-6,6) C19(-6,6.8) C20(-6,7.6) D1(-5.2,-7.6) D2(-5.2,-6.8) D3(-5.2,-6) D4(-5.2,-5.2) D5(-5.2,-4.4) D6(-5.2,-3.6) D7(-5.2,-2.8) D8(-5.2,-2) D9(-5.2,-1.2) D10(-5.2,-0.4) D11(-5.2,0.4) D12(-5.2,1.2) D13(-5.2,2) D14(-5.2,2.8) D15(-5.2,3.6) D16(-5.2,4.4) D17(-5.2,5.2) D18(-5.2,6) D19(-5.2,6.8) D20(-5.2,7.6) E1(-4.4,-7.6) E2(-4.4,-6.8) E3(-4.4,-6) E4(-4.4,-5.2) E5(-4.4,-4.4) E6(-4.4,-3.6) E7(-4.4,-2.8) E8(-4.4,-2) E9(-4.4,-1.2) E10(-4.4,-0.4) E11(-4.4,0.4) E12(-4.4,1.2) E13(-4.4,2) E14(-4.4,2.8) E15(-4.4,3.6) E16(-4.4,4.4) E17(-4.4,5.2) E18(-4.4,6) E19(-4.4,6.8) E20(-4.4,7.6) F1(-3.6,-7.6) F2(-3.6,-6.8) F3(-3.6,-6) F4(-3.6,-5.2) F5(-3.6,-4.4) F6(-3.6,-3.6) F7(-3.6,-2.8) F8(-3.6,-2) F9(-3.6,-1.2) F10(-3.6,-0.4) F11(-3.6,0.4) F12(-3.6,1.2) F13(-3.6,2) F14(-3.6,2.8) F15(-3.6,3.6) F16(-3.6,4.4) F17(-3.6,5.2) F18(-3.6,6) F19(-3.6,6.8) F20(-3.6,7.6) G1(-2.8,-7.6) G2(-2.8,-6.8) G3(-2.8,-6) G4(-2.8,-5.2) G5(-2.8,-4.4) G6(-2.8,-3.6) G7(-2.8,-2.8) G8(-2.8,-2) G9(-2.8,-1.2) G10(-2.8,-0.4) G11(-2.8,0.4) G12(-2.8,1.2) G13(-2.8,2) G14(-2.8,2.8) G15(-2.8,3.6) G16(-2.8,4.4) G17(-2.8,5.2) G18(-2.8,6) G19(-2.8,6.8) G20(-2.8,7.6) H1(-2,-7.6) H2(-2,-6.8) H3(-2,-6) H4(-2,-5.2) H5(-2,-4.4) H6(-2,-3.6) H7(-2,-2.8) H8(-2,-2) H9(-2,-1.2) H10(-2,-0.4) H11(-2,0.4) H12(-2,1.2) H13(-2,2) H14(-2,2.8) H15(-2,3.6) H16(-2,4.4) H17(-2,5.2) H18(-2,6) H19(-2,6.8) H20(-2,7.6) J1(-1.2,-7.6) J2(-1.2,-6.8) J3(-1.2,-6) J4(-1.2,-5.2) J5(-1.2,-4.4) J6(-1.2,-3.6) J7(-1.2,-2.8) J8(-1.2,-2) J9(-1.2,-1.2) J10(-1.2,-0.4) J11(-1.2,0.4) J12(-1.2,1.2) J13(-1.2,2) J14(-1.2,2.8) J15(-1.2,3.6) J16(-1.2,4.4) J17(-1.2,5.2) J18(-1.2,6) J19(-1.2,6.8) J20(-1.2,7.6) K1(-0.4,-7.6) K2(-0.4,-6.8) K3(-0.4,-6) K4(-0.4,-5.2) K5(-0.4,-4.4) K6(-0.4,-3.6) K7(-0.4,-2.8) K8(-0.4,-2) K9(-0.4,-1.2) K10(-0.4,-0.4) K11(-0.4,0.4) K12(-0.4,1.2) K13(-0.4,2) K14(-0.4,2.8) K15(-0.4,3.6) K16(-0.4,4.4) K17(-0.4,5.2) K18(-0.4,6) K19(-0.4,6.8) K20(-0.4,7.6) L1(0.4,-7.6) L2(0.4,-6.8) L3(0.4,-6) L4(0.4,-5.2) L5(0.4,-4.4) L6(0.4,-3.6) L7(0.4,-2.8) L8(0.4,-2) L9(0.4,-1.2) L10(0.4,-0.4) L11(0.4,0.4) L12(0.4,1.2) L13(0.4,2) L14(0.4,2.8) L15(0.4,3.6) L16(0.4,4.4) L17(0.4,5.2) L18(0.4,6) L19(0.4,6.8) L20(0.4,7.6) M1(1.2,-7.6) M2(1.2,-6.8) M3(1.2,-6) M4(1.2,-5.2) M5(1.2,-4.4) M6(1.2,-3.6) M7(1.2,-2.8) M8(1.2,-2) M9(1.2,-1.2) M10(1.2,-0.4) M11(1.2,0.4) M12(1.2,1.2) M13(1.2,2) M14(1.2,2.8) M15(1.2,3.6) M16(1.2,4.4) M17(1.2,5.2) M18(1.2,6) M19(1.2,6.8) M20(1.2,7.6) N1(2,-7.6) N2(2,-6.8) N3(2,-6) N4(2,-5.2) N5(2,-4.4) N6(2,-3.6) N7(2,-2.8) N8(2,-2) N9(2,-1.2) N10(2,-0.4) N11(2,0.4) N12(2,1.2) N13(2,2) N14(2,2.8) N15(2,3.6) N16(2,4.4) N17(2,5.2) N18(2,6) N19(2,6.8) N20(2,7.6) P1(2.8,-7.6) P2(2.8,-6.8) P3(2.8,-6) P4(2.8,-5.2) P5(2.8,-4.4) P6(2.8,-3.6) P7(2.8,-2.8) P8(2.8,-2) P9(2.8,-1.2) P10(2.8,-0.4) P11(2.8,0.4) P12(2.8,1.2) P13(2.8,2) P14(2.8,2.8) P15(2.8,3.6) P16(2.8,4.4) P17(2.8,5.2) P18(2.8,6) P19(2.8,6.8) P20(2.8,7.6) R1(3.6,-7.6) R2(3.6,-6.8) R3(3.6,-6) R4(3.6,-5.2) R5(3.6,-4.4) R6(3.6,-3.6) R7(3.6,-2.8) R8(3.6,-2) R9(3.6,-1.2) R10(3.6,-0.4) R11(3.6,0.4) R12(3.6,1.2) R13(3.6,2) R14(3.6,2.8) R15(3.6,3.6) R16(3.6,4.4) R17(3.6,5.2) R18(3.6,6) R19(3.6,6.8) R20(3.6,7.6) T1(4.4,-7.6) T2(4.4,-6.8) T3(4.4,-6) T4(4.4,-5.2) T5(4.4,-4.4) T6(4.4,-3.6) T7(4.4,-2.8) T8(4.4,-2) T9(4.4,-1.2) T10(4.4,-0.4) T11(4.4,0.4) T12(4.4,1.2) T13(4.4,2) T14(4.4,2.8) T15(4.4,3.6) T16(4.4,4.4) T17(4.4,5.2) T18(4.4,6) T19(4.4,6.8) T20(4.4,7.6) U1(5.2,-7.6) U2(5.2,-6.8) U3(5.2,-6) U4(5.2,-5.2) U5(5.2,-4.4) U6(5.2,-3.6) U7(5.2,-2.8) U8(5.2,-2) U9(5.2,-1.2) U10(5.2,-0.4) U11(5.2,0.4) U12(5.2,1.2) U13(5.2,2) U14(5.2,2.8) U15(5.2,3.6) U16(5.2,4.4) U17(5.2,5.2) U18(5.2,6) U19(5.2,6.8) U20(5.2,7.6) V1(6,-7.6) V2(6,-6.8) V3(6,-6) V4(6,-5.2) V5(6,-4.4) V6(6,-3.6) V7(6,-2.8) V8(6,-2) V9(6,-1.2) V10(6,-0.4) V11(6,0.4) V12(6,1.2) V13(6,2) V14(6,2.8) V15(6,3.6) V16(6,4.4) V17(6,5.2) V18(6,6) V19(6,6.8) V20(6,7.6) W1(6.8,-7.6) W2(6.8,-6.8) W3(6.8,-6) W4(6.8,-5.2) W5(6.8,-4.4) W6(6.8,-3.6) W7(6.8,-2.8) W8(6.8,-2) W9(6.8,-1.2) W10(6.8,-0.4) W11(6.8,0.4) W12(6.8,1.2) W13(6.8,2) W14(6.8,2.8) W15(6.8,3.6) W16(6.8,4.4) W17(6.8,5.2) W18(6.8,6) W19(6.8,6.8) W20(6.8,7.6) Y1(7.6,-7.6) Y2(7.6,-6.8) Y3(7.6,-6) Y4(7.6,-5.2) Y5(7.6,-4.4) Y6(7.6,-3.6) Y7(7.6,-2.8) Y8(7.6,-2) Y9(7.6,-1.2) Y10(7.6,-0.4) Y11(7.6,0.4) Y12(7.6,1.2) Y13(7.6,2) Y14(7.6,2.8) Y15(7.6,3.6) Y16(7.6,4.4) Y17(7.6,5.2) Y18(7.6,6) Y19(7.6,6.8) Y20(7.6,7.6)
